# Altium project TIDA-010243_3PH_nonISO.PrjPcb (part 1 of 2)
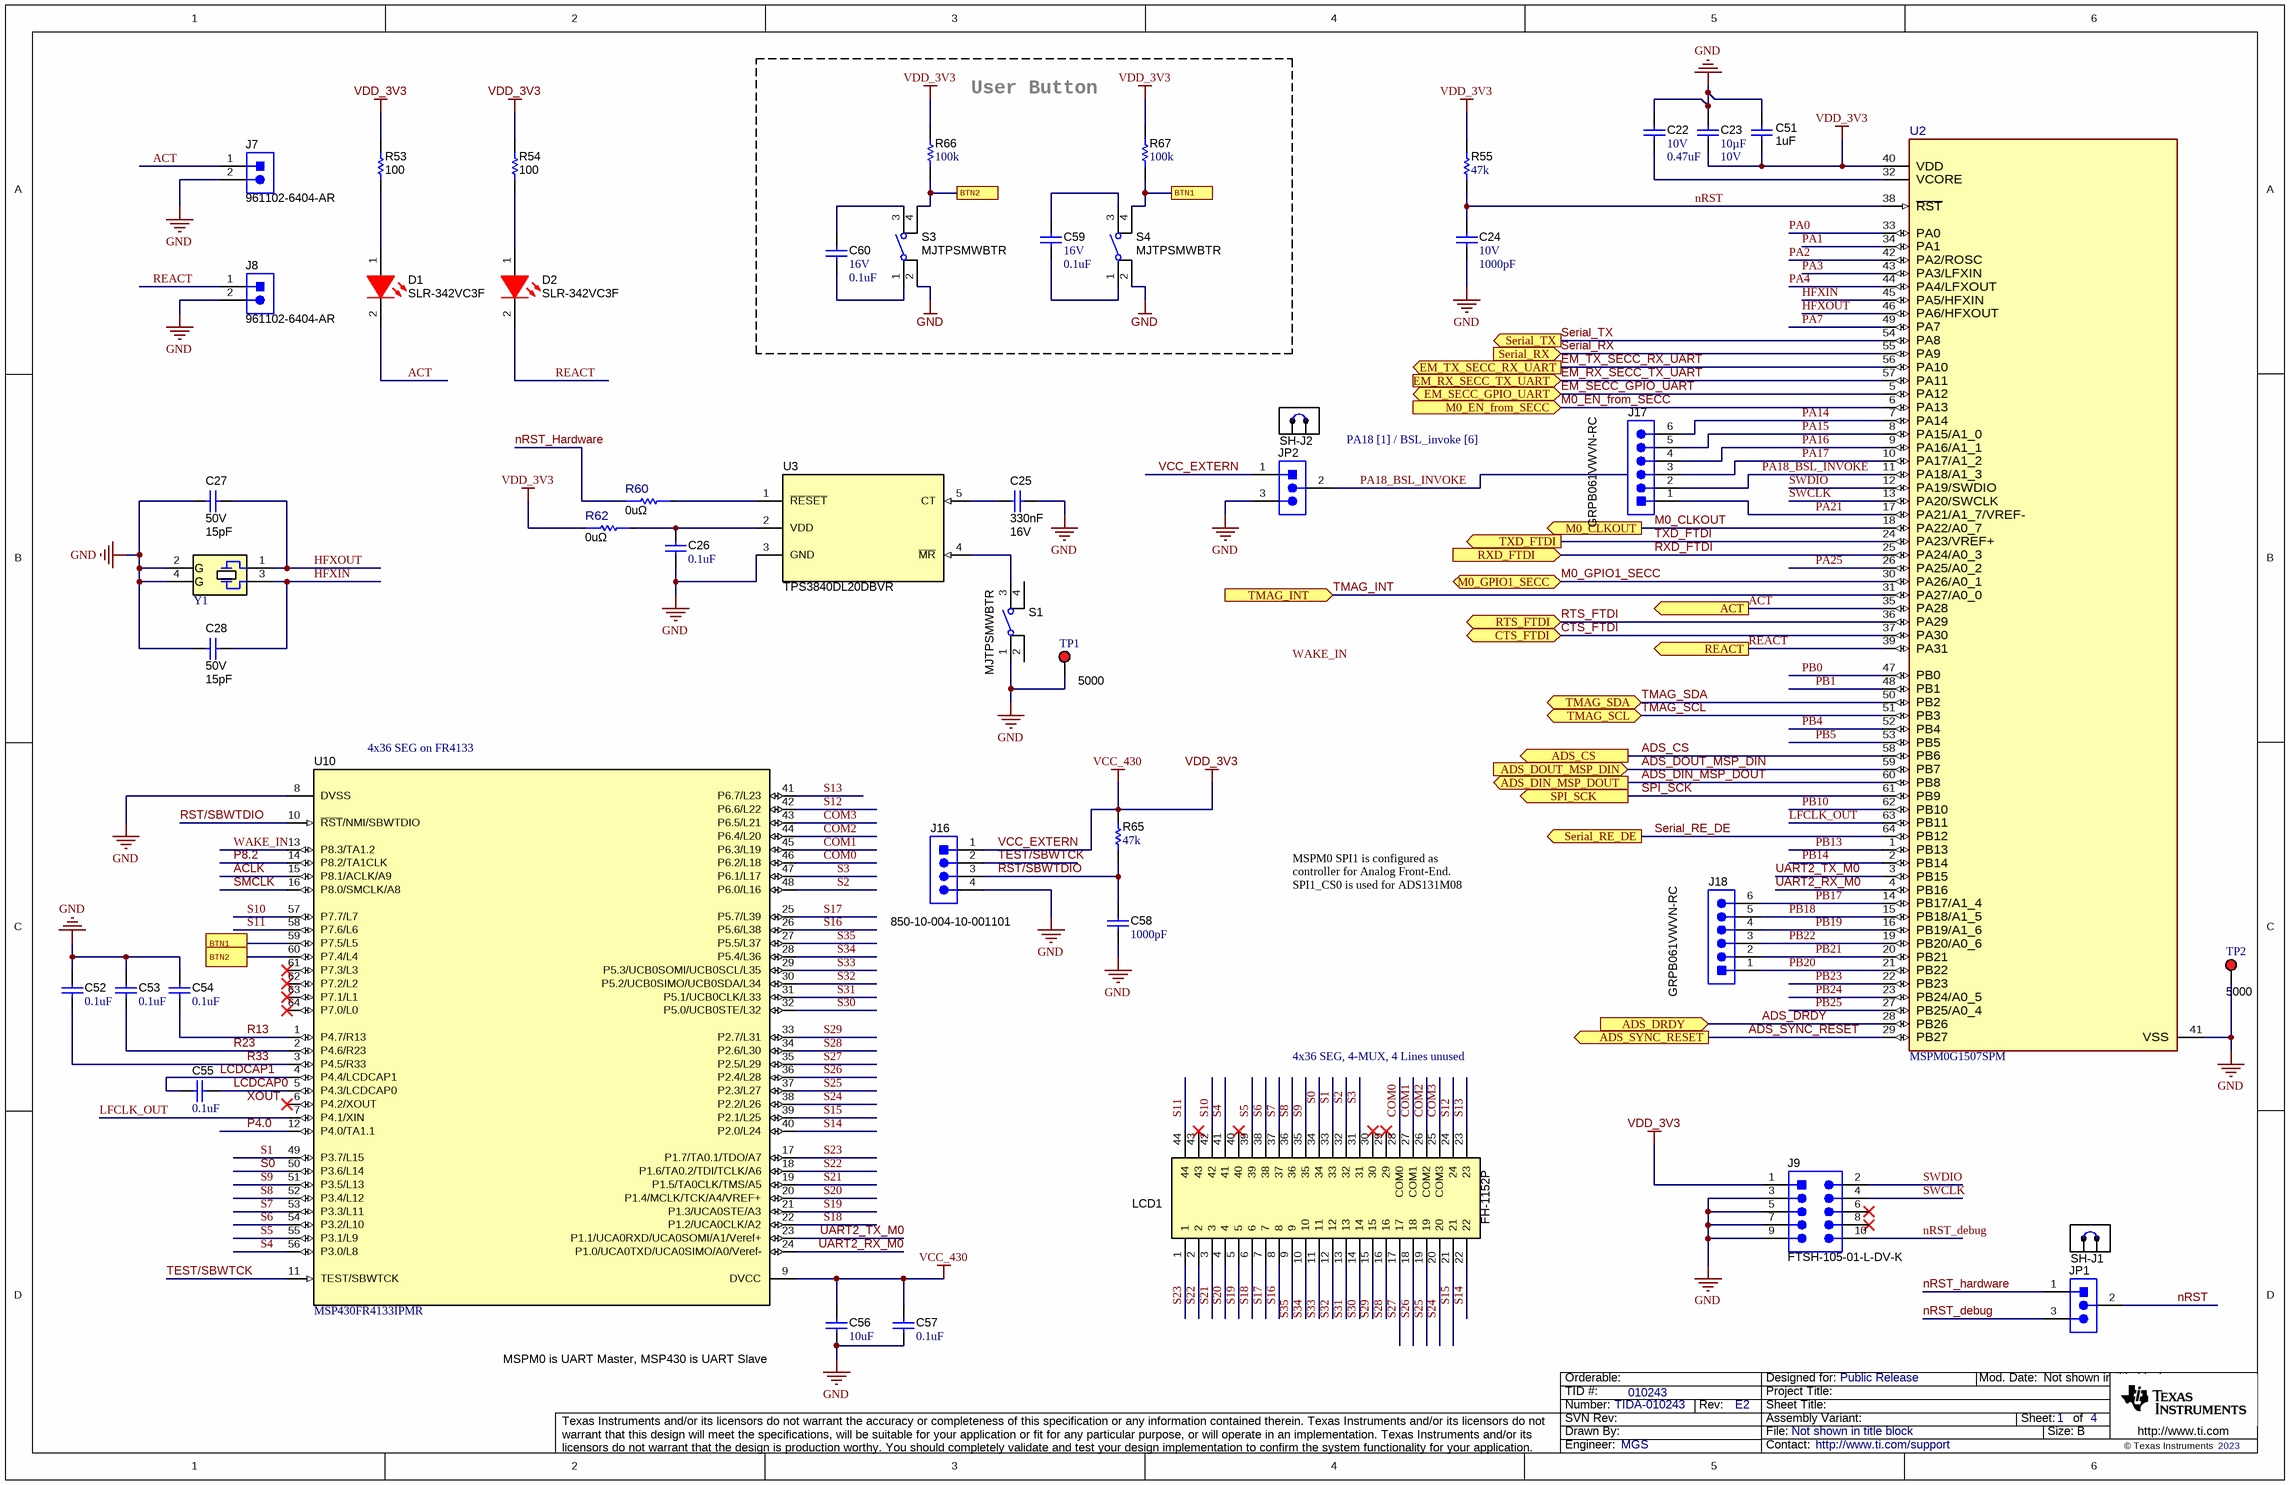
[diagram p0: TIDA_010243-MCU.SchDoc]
3-phase E-meter with CTs: Change in menu Project|Project Options|Parameters; CopyrightYear: 2023; PCB_Layout: a0797195; PCB_Rev: E2; PRJ_Customer: Public Release; PRJ_Engineer: MGS; PRJ_Number: TIDA-010243; SCH_Rev: E2; TechSupport: http://www.ti.com/support; TID: 010243
4 sheets, 215 parts. Net scope: flat (ports and power ports of the same name join across sheets).
Board file: TIDA-010243_3PH_CTnonISO.PcbDoc
Sheets:
  TIDA_010243-MCU.SchDoc
  TIDA-010243-AFE.SchDoc
  TIDA-010243_Interfaces.SchDoc
  TIDA-010243_Hardware.SchDoc

## Sheet TIDA_010243-MCU.SchDoc
size 431 x 279 mm; Date: Not shown in title block; ApprovedBy: Not shown in title block; CheckedBy: Not shown in title block; Author: Not shown in title block; CompanyName: Not shown in title block; Engineer: Not shown in title block; Organization: Not shown in title block; Address1: Not shown in title block; Address2: Not shown in title block; Address3: Not shown in title block; Address4: Not shown in title block; DocumentNumber: 1; Revision: Use project parameter SCH_Rev; SheetNumber: 1; SheetTotal: 4; PageSetup: Record=PageOptions¦CenterHorizontal=True¦CenterVertical=True¦PrintScale=1.00¦XCorrection=1.00¦YCorrection=1.00¦PrintKind=0¦BorderSize=5000000¦LeftOffset=0¦BottomOffset=0¦Orientation=2¦PaperLength=1000¦PaperWidth=1000¦Scale=100¦PaperSource=15¦PrintQuality=600¦MediaType=1¦DitherType=10¦PaperKind=Letter¦PrintScaleMode=1

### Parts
C22  VDC_V: 10V  ValueDisplayed: 0.47uF  [0603]  (hidden comment: GRM188R61A474KA61D)
C23  ValueDisplayed: 10µF  VDC_V: 10V  [0603]  (hidden comment: GRM188R61A106KAALD)
C24  VDC_V: 10V  ValueDisplayed: 1000pF  [0402]  (hidden comment: GRM155R61A102KA01D)
C25  Cap_F: 330nF  VDC_V: 16V  [0603]  (hidden comment: GRM188R71C334KA01D)
C26  value 0.1uF  [0402]  (hidden comment: GCM155R71H104KE02D)
C27  VDC_V: 50V  ValueDisplayed: 15pF  [0402]  (hidden comment: GRM1555C1H150JA01D)
C28  VDC_V: 50V  ValueDisplayed: 15pF  [0402]  (hidden comment: GRM1555C1H150JA01D)
C51  ValueDisplayed: 1uF  [0603]  (hidden comment: C0603C105K3RACTU)
C52  ValueDisplayed: 0.1uF  [0402]  (hidden comment: GCM155R71A104KA55D)
C53  ValueDisplayed: 0.1uF  [0402]  (hidden comment: GCM155R71A104KA55D)
C54  ValueDisplayed: 0.1uF  [0402]  (hidden comment: GCM155R71A104KA55D)
C55  ValueDisplayed: 0.1uF  [0402]  (hidden comment: GCM155R71A104KA55D)
C56  ValueDisplayed: 10uF  [0603]  (hidden comment: GRM188R61A106ME69D)
C57  ValueDisplayed: 0.1uF  [0402]  (hidden comment: GCM155R71A104KA55D)
C58  ValueDisplayed: 1000pF  [0402]  (hidden comment: 885012205044)
C59  VDC_V: 16V  ValueDisplayed: 0.1uF  [0402]  (hidden comment: C0402C104K4RACAUTO)
C60  VDC_V: 16V  ValueDisplayed: 0.1uF  [0402]  (hidden comment: C0402C104K4RACAUTO)
D1  SLR-342VC3F  [SLR-342_Red]
D2  SLR-342VC3F  [SLR-342_Red]
J7  961102-6404-AR  [3M_961102-6404-AR]
J8  961102-6404-AR  [3M_961102-6404-AR]
J9  FTSH-105-01-L-DV-K  [Samtec_FTSH-105-01-x-DV-K]
J16  850-10-004-10-001101  [Preci-dip_850-xx-004-10-001101]
J17  GRPB061VWVN-RC  [Sullins_GRPB061VWVN-RC]
J18  GRPB061VWVN-RC  [Sullins_GRPB061VWVN-RC]
JP1  TSW-103-07-G-S  [TSW-103-07-G-S]  (value not drawn)
JP2  TSW-103-07-G-S  [TSW-103-07-G-S]  (value not drawn)
LCD1  FH-1152P  [ADKOM_FH-1152P]
R53  ValueDisplayed: 100  [0603]  (hidden comment: RC0603FR-07100RL)
R54  ValueDisplayed: 100  [0603]  (hidden comment: RC0603FR-07100RL)
R55  ValueDisplayed: 47k  [0402]  (hidden comment: CRCW040247K0JNED)
R60  value 0uΩ  [FP-CR0402-10W-000T_0402-MFG]  (hidden comment: CR0402-10W-000T)
R62  value 0uΩ  [FP-CR0402-10W-000T_0402-MFG]  (hidden comment: CR0402-10W-000T)
R65  ValueDisplayed: 47k  [0402S]  (hidden comment: CRCW040247K0JNED)
R66  ValueDisplayed: 100k  [0402]  (hidden comment: CRCW0402100KFKED)
R67  ValueDisplayed: 100k  [0402]  (hidden comment: CRCW0402100KFKED)
S1  MJTPSMWBTR  [SW_MJTPSMWB]
S3  MJTPSMWBTR  [SW_MJTPSMWB]
S4  MJTPSMWBTR  [SW_MJTPSMWB]
SH-J1  881545-2  [TE_881545-2]  (value not drawn)  (mechanical)
SH-J2  881545-2  [TE_881545-2]  (value not drawn)  (mechanical)
TP1  5000  [Keystone5000]
TP2  5000  [Keystone5000]
U2  MSPM0G1507SPM  [PM0064A-MFG]
U3  TPS3840DL20DBVR  [DBV0005A_N]
U10  MSP430FR4133IPMR  [PM0064A_L]
Y1  FA-238 16.3840MB-K  [Epson_FA-238]  (value not drawn)

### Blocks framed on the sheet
User Button: C59 C60 R66 R67 S3 S4

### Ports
ACT (out), ADS_CS (out), ADS_DIN_MSP_DOUT (out), ADS_DOUT_MSP_DIN (in), ADS_DRDY (in), ADS_SYNC_RESET (out), BTN1, BTN2, CTS_FTDI (bidir), EM_RX_SECC_TX_UART (in), EM_SECC_GPIO_UART (bidir), EM_TX_SECC_RX_UART (out), M0_CLKOUT (out), M0_EN_from_SECC (in), M0_GPIO1_SECC (bidir), REACT (out), RTS_FTDI (bidir), RXD_FTDI (in), Serial_RE_DE (out), Serial_RX (in), Serial_TX (out), SPI_SCK (out), TMAG_INT (in), TMAG_SCL (bidir), TMAG_SDA (bidir), TXD_FTDI (out)

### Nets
GND: C22.1 C23.1 C24.2 C25.1 C26.1 C27.2 C28.2 C51.2 C52.1 C53.1 C54.1 C56.2 C57.2 C58.2 J7.2 J8.2 J9.3 J9.5 J9.7 J9.9 J16.4 JP2.3 S1.1 S3.2 S4.2 TP1.1 TP2.1 U2.41(VSS) U3.3(GND) U10.8(DVSS) Y1.2(GND) Y1.4(GND)
VCC_EXTERN: C23.2 C51.1 C56.1 C57.1 J9.1 J16.1 JP2.1 R53.2 R54.2 R55.2 R62.1 R65.2 R66.2 R67.2 U2.40(VDD) U10.9(DVCC)  [also labelled VCC_430, VDD_3V3]
ACLK: U10.15(P8.1/ACLK/A9)
ACT: D1.2(K) J7.1 U2.35(PA28) ; port ACT
ADS_CS: U2.58(PB6) ; port ADS_CS
ADS_DIN_MSP_DOUT: U2.60(PB8) ; port ADS_DIN_MSP_DOUT
ADS_DOUT_MSP_DIN: U2.59(PB7) ; port ADS_DOUT_MSP_DIN
ADS_DRDY: U2.28(PB26) ; port ADS_DRDY
ADS_SYNC_RESET: U2.29(PB27) ; port ADS_SYNC_RESET
BTN1: R67.1 S4.4 U10.59(P7.5/L5) ; port BTN1
BTN2: R66.1 S3.4 U10.60(P7.4/L4) ; port BTN2
COM0: LCD1.28(COM0) U10.46(P6.2/L18)
COM1: LCD1.27(COM1) U10.45(P6.3/L19)
COM2: LCD1.26(COM2) U10.44(P6.4/L20)
COM3: LCD1.25(COM3) U10.43(P6.5/L21)
CTS_FTDI: U2.37(PA30) ; port CTS_FTDI
EM_RX_SECC_TX_UART: U2.57(PA11) ; port EM_RX_SECC_TX_UART
EM_SECC_GPIO_UART: U2.5(PA12) ; port EM_SECC_GPIO_UART
EM_TX_SECC_RX_UART: U2.56(PA10) ; port EM_TX_SECC_RX_UART
HFXIN: C28.1 U2.45(PA5/HFXIN) Y1.3
HFXOUT: C27.1 U2.46(PA6/HFXOUT) Y1.1
LCDCAP0: C55.2 U10.5(P4.3/LCDCAP0)
LCDCAP1: C55.1 U10.4(P4.4/LCDCAP1)
LFCLK_OUT: U2.63(PB11) U10.7(P4.1/XIN)
M0_CLKOUT: U2.18(PA22/A0_7) ; port M0_CLKOUT
M0_EN_from_SECC: U2.6(PA13) ; port M0_EN_from_SECC
M0_GPIO1_SECC: U2.30(PA26/A0_1) ; port M0_GPIO1_SECC
nRST: C24.1 JP1.2 R55.1 U2.38(~{RST})
nRST_debug: J9.10 JP1.3
nRST_Hardware: JP1.1 R60.1
P4.0: U10.12(P4.0/TA1.1)
P8.2: U10.14(P8.2/TA1CLK)
PA0: U2.33(PA0)
PA1: U2.34(PA1)
PA2: U2.42(PA2/ROSC)
PA3: U2.43(PA3/LFXIN)
PA4: U2.44(PA4/LFXOUT)
PA7: U2.49(PA7)
PA14: J17.6 U2.7(PA14)
PA15: J17.5 U2.8(PA15/A1_0)
PA16: J17.4 U2.9(PA16/A1_1)
PA17: J17.3 U2.10(PA17/A1_2)
PA18_BSL_INVOKE: J17.2 JP2.2 U2.11(PA18/A1_3)
PA21: J17.1 U2.17(PA21/A1_7/VREF-)
PA25: U2.26(PA25/A0_2)
PB0: U2.47(PB0)
PB1: U2.48(PB1)
PB4: U2.52(PB4)
PB5: U2.53(PB5)
PB10: U2.62(PB10)
PB13: U2.1(PB13)
PB14: U2.2(PB14)
PB17: J18.6 U2.14(PB17/A1_4)
PB18: J18.5 U2.15(PB18/A1_5)
PB19: J18.4 U2.16(PB19/A1_6)
PB20: J18.1 U2.21(PB22)
PB21: J18.2 U2.20(PB21)
PB22: J18.3 U2.19(PB20/A0_6)
PB23: U2.22(PB23)
PB24: U2.23(PB24/A0_5)
PB25: U2.27(PB25/A0_4)
R13: C54.2 U10.1(P4.7/R13)
R23: C53.2 U10.2(P4.6/R23)
R33: C52.2 U10.3(P4.5/R33)
REACT: D2.2(K) J8.1 U2.39(PA31) ; port REACT
RST/SBWTDIO: C58.1 J16.3 R65.1 U10.10(~{RST}/NMI/SBWTDIO)
RTS_FTDI: U2.36(PA29) ; port RTS_FTDI
RXD_FTDI: U2.25(PA24/A0_3) ; port RXD_FTDI
S0: LCD1.34 U10.50(P3.6/L14)
S1: LCD1.33 U10.49(P3.7/L15)
S2: LCD1.32 U10.48(P6.0/L16)
S3: LCD1.31 U10.47(P6.1/L17)
S4: LCD1.41 U10.56(P3.0/L8)
S5: LCD1.39 U10.55(P3.1/L9)
S6: LCD1.38 U10.54(P3.2/L10)
S7: LCD1.37 U10.53(P3.3/L11)
S8: LCD1.36 U10.52(P3.4/L12)
S9: LCD1.35 U10.51(P3.5/L13)
S10: LCD1.42 U10.57(P7.7/L7)
S11: LCD1.44 U10.58(P7.6/L6)
S12: LCD1.24 U10.42(P6.6/L22)
S13: LCD1.23 U10.41(P6.7/L23)
S14: LCD1.22 U10.40(P2.0/L24)
S15: LCD1.21 U10.39(P2.1/L25)
S16: LCD1.8 U10.26(P5.6/L38)
S17: LCD1.7 U10.25(P5.7/L39)
S18: LCD1.6 U10.22(P1.2/UCA0CLK/A2)
S19: LCD1.5 U10.21(P1.3/UCA0STE/A3)
S20: LCD1.4 U10.20(P1.4/MCLK/TCK/A4/VREF+)
S21: LCD1.3 U10.19(P1.5/TA0CLK/TMS/A5)
S22: LCD1.2 U10.18(P1.6/TA0.2/TDI/TCLK/A6)
S23: LCD1.1 U10.17(P1.7/TA0.1/TDO/A7)
S24: LCD1.20 U10.38(P2.2/L26)
S25: LCD1.19 U10.37(P2.3/L27)
S26: LCD1.18 U10.36(P2.4/L28)
S27: LCD1.17 U10.35(P2.5/L29)
S28: LCD1.16 U10.34(P2.6/L30)
S29: LCD1.15 U10.33(P2.7/L31)
S30: LCD1.14 U10.32(P5.0/UCB0STE/L32)
S31: LCD1.13 U10.31(P5.1/UCB0CLK/L33)
S32: LCD1.12 U10.30(P5.2/UCB0SIMO/UCB0SDA/L34)
S33: LCD1.11 U10.29(P5.3/UCB0SOMI/UCB0SCL/L35)
S34: LCD1.10 U10.28(P5.4/L36)
S35: LCD1.9 U10.27(P5.5/L37)
Serial_RE_DE: U2.64(PB12) ; port Serial_RE_DE
Serial_RX: U2.55(PA9) ; port Serial_RX
Serial_TX: U2.54(PA8) ; port Serial_TX
SMCLK: U10.16(P8.0/SMCLK/A8)
SPI_SCK: U2.61(PB9) ; port SPI_SCK
SWCLK: J9.4 U2.13(PA20/SWCLK)
SWDIO: J9.2 U2.12(PA19/SWDIO)
TEST/SBWTCK: J16.2 U10.11(TEST/SBWTCK)
TMAG_INT: U2.31(PA27/A0_0) ; port TMAG_INT
TMAG_SCL: U2.51(PB3) ; port TMAG_SCL
TMAG_SDA: U2.50(PB2) ; port TMAG_SDA
TXD_FTDI: U2.24(PA23/VREF+) ; port TXD_FTDI
UART2_RX_M0: U2.4(PB16) U10.24(P1.0/UCA0TXD/UCA0SIMO/A0/Veref-)
UART2_TX_M0: U2.3(PB15) U10.23(P1.1/UCA0RXD/UCA0SOMI/A1/Veref+)
WAKE_IN: U10.13(P8.3/TA1.2)
NetC22_2: C22.2 U2.32(VCORE)
NetC25_2: C25.2 U3.5(CT)
NetC26_2: C26.2 R62.2 U3.2(VDD)
NetC59_1: C59.1 S4.3
NetC59_2: C59.2 S4.1
NetC60_1: C60.1 S3.3
NetC60_2: C60.2 S3.1
NetD1_1: D1.1(A) R53.1
NetD2_1: D2.1(A) R54.1
NetR60_2: R60.2 U3.1(~{RESET})
NetS1_3: S1.3 U3.4(~{MR})

Not connected (* = marked no-connect by the designer): J9 6* 8*; LCD1 29* 30* 40* 43*; S1 2 4; U10 6(P4.2/XOUT)* 61(P7.3/L3)* 62(P7.2/L2)* 63(P7.1/L1)* 64(P7.0/L0)*

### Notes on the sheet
- PA18 [1] / BSL_invoke [6]
- (near U10) 4x36 SEG on FR4133
- MSPM0 SPI1 is configured as controller for Analog Front-End. SPI1_CS0 is used for ADS131M08
- 4x36 SEG, 4-MUX, 4 Lines unused
- MSPM0 is UART Master, MSP430 is UART Slave
- Labels drawn without touching a wire or pin: WAKE_IN, XOUT

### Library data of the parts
C22 = CMP-0007328-5: CAP, CERM, 0.47 uF, 10 V, +/- 10%, X5R, 0603; Manufacturer: MuRata; TaMin_C: -55°C; Polarized: N; SizeAreaWB_mm2: 4.68; Value1: Unknown; U/M: EA; Value: 0.47uF; TaMax_C: 85°C; SizeZ_mm: 1; SizeX_mm: 1.6; SizeY_mm: 0.8; SizeArea_mm2: 1.28; Cap_F: 470nF; AEC Category: Q200
C23 = CMP-0086193-1: CAP, CERM, 10 µF, 10 V,+/- 10%, X5R, 0603; Manufacturer: MuRata; SizeArea_mm2: 1.28; SizeY_mm: 0.8; TaMax_C: 85°C; TaMin_C: -55°C; Polarized: N; SizeAreaWB_mm2: 4.68; SizeZ_mm: 1; SizeX_mm: 1.6; AEC Category: Q200; U/M: EA; Value: 10uF
C24 = CMP-0006560-2: CAP, CERM, 1000 pF, 10 V, +/- 10%, X5R, 0402; Manufacturer: MuRata; TaMin_C: -55°C; Polarized: N; SizeAreaWB_mm2: 3; Value1: Unknown; U/M: EA; Value: 1000pF; TaMax_C: 85°C; SizeZ_mm: 0.6; SizeX_mm: 1; SizeY_mm: 0.5; Cap_F: 1nF; AEC Category: Q200
C25 = CMP-0007393-1: CAP, CERM, 0.33 uF, 16 V, +/- 10%, X7R, 0603; Manufacturer: MuRata; TaMin_C: -55°C; Polarized: N; SizeAreaWB_mm2: 4.68; Value1: Unknown; U/M: EA; Value: 0.33uF; TaMax_C: 125°C; SizeZ_mm: 1; SizeX_mm: 1.6; SizeY_mm: 0.8; SizeArea_mm2: 1.28; AEC Category: Q200
C26 = CMP-0006356-2: CAP, CERM, 0.1 uF, 50 V, +/- 10%, X7R, AEC-Q200 Grade 1, 0402; Manufacturer: MuRata; TaMin_C: -55°C; Polarized: N; SizeAreaWB_mm2: 3; Value1: Unknown; U/M: EA; TaMax_C: 125°C; SizeZ_mm: 0.6; SizeX_mm: 1; SizeY_mm: 0.5; Value2: 50V; AEC Qualified: Y; AEC Category: Q200; Cap_F: 100nF
C27 C28 = CMP-0006420-2: CAP, CERM, 15 pF, 50 V, +/- 5%, C0G/NP0, 0402; Manufacturer: MuRata; TaMin_C: -55°C; Polarized: N; SizeAreaWB_mm2: 3; Value1: Unknown; U/M: EA; Value: 15pF; TaMax_C: 125°C; SizeZ_mm: 0.6; SizeX_mm: 1; SizeY_mm: 0.5; AEC Category: Q200
C51 = CMP-0006867-4: CAP, CERM, 1 uF, 25 V, +/- 10%, X7R, 0603; Manufacturer: Kemet; TaMin_C: -55°C; Polarized: N; SizeAreaWB_mm2: 4.68; Value1: Unknown; U/M: EA; Value: 1uF; TaMax_C: 125°C; SizeZ_mm: 1; SizeX_mm: 1.6; SizeY_mm: 0.8; Value2: 25V; SizeArea_mm2: 1.28; CompType: Capacitor; Cap_F: 1µF; AEC Category: Q200
C52-C55 C57 = CMP-0006350-2: CAP, CERM, 0.1 uF, 10 V, +/- 10%, X7R, AEC-Q200 Grade 1, 0402; Manufacturer: MuRata; Polarized: N; Value: 0.1uF; U/M: EA; Cap_F: 100nF; Value1: Unknown; VDC_V: 10V; TaMin_C: -55°C; TaMax_C: 125°C; SizeAreaWB_mm2: 3; SizeZ_mm: 0.6; SizeX_mm: 1; SizeY_mm: 0.5; AEC Qualified: Y; AEC Category: Q200
C56 = CMP-0007318-5: CAP, CERM, 10 uF, 10 V, +/- 20%, X5R, 0603; Manufacturer: MuRata; Polarized: N; Value: 10uF; U/M: EA; Cap_F: 10µF; Value1: Unknown; VDC_V: 10V; TaMin_C: -55°C; TaMax_C: 85°C; SizeAreaWB_mm2: 4.68; SizeZ_mm: 1; SizeX_mm: 1.6; SizeY_mm: 0.8; SizeArea_mm2: 1.28; AEC Category: Q200
C58 = CMP-0006229-2: CAP, CERM, 1000 pF, 25 V, +/- 10%, X7R, 0402; Manufacturer: Wurth Elektronik; Polarized: N; Value: 1000pF; U/M: EA; Cap_F: 1nF; Value1: Unknown; VDC_V: 25V; TaMin_C: -55°C; TaMax_C: 125°C; SizeAreaWB_mm2: 3; SizeZ_mm: 0.6; SizeX_mm: 1; SizeY_mm: 0.5; AEC Category: Q200
C59 C60 = CMP-0006237-2: CAP, CERM, 0.1 uF, 16 V, +/- 10%, X7R, AEC-Q200 Grade 1, 0402; Manufacturer: Kemet; TaMin_C: -55°C; Polarized: N; SizeAreaWB_mm2: 3; Value1: Unknown; U/M: EA; Value: 0.1uF; TaMax_C: 125°C; SizeZ_mm: 0.6; SizeX_mm: 1; SizeY_mm: 0.5; AEC Qualified: Y; Cap_F: 100nF; AEC Category: Q200
D1 D2 = CMP-0079280-1: LED, Red, TH; Manufacturer: Rohm; SizeAreaWB_mm2: 23.04; Vr_V: 3V; Power_TotalModule: 60mW; Angle: 40; SizeArea_mm2: 14.44; Ir_A: 10µA; SizeZ_mm: 6.35; Io_A: 10mA; Vf_V: 2V; SizeY_mm: 3.8; Value1: 0.06W; Type: GaAsP on GaP
J7 J8 = CMP-0075197-1: Header, 2.54mm, 2x1, TH; Manufacturer: 3M; CNHeader: True; Current_A: 2A; Green_Lifecycle: Active; Shrouded: N; Gender: Male; Green_REACh: Passed; Voltage_V: 1kV; Row_Count: 1; Pitch_mm: 2.54; ContactFinish: Gold; CT: False; Cert_UL: Y
J9 = CMP-0075634-2: Header(Shrouded), 1.27mm, 5x2, Gold, SMT; Manufacturer: Samtec; Pitch_mm: 1.27; Gender: Male; Cert_CSA: Y; Current_A: 3.3A; Row_Count: 2
J16 = CMP-0074999-1: Header, 50mil, 4x1, Gold, TH; Manufacturer: Preci-Dip; CT: False; CNHeader: True
J17 J18 = CMP-0054561-1: Header, 50mil, 6x1, Gold,  TH; Manufacturer: Sullins Connector Solutions; CT: FALSE; CNHeader: TRUE
JP1 JP2 = CMP-0075407-2: Header, 100mil, 3x1, Gold, TH; Manufacturer: Samtec; Pitch_mm: 2.54; Cert_VDE: N; Gender: Male; Cert_CSA: Y; Voltage_V: 550V; Green_REACh: Passed; Current_A: 6.3A; Green_Lifecycle: Active; Row_Count: 1
LCD1 = CMP-0079272-1: 160 Segment LCD Display, TH; Manufacturer: Adkom Elektronik; SizeArea_mm2: 1970.56; SizeAreaWB_mm2: 2164.14; SizeY_mm: 64; SizeZ_mm: 3.1; SizeX_mm: 30.79
R53 R54 = CMP-0022736-2: RES, 100, 1%, 0.1 W, 0603; Manufacturer: Yageo America; Power_W: 100mW; TempCo: 200 ppm/C; Value_Code: 100R; U/M: EA; Value: 100; EIA_Code: E96; SizeX_mm: 1.6; SizeY_mm: 0.8; SizeZ_mm: 1; Value2: 0.1W; SizeArea_mm2: 1.28; VDC_V: 150V; AEC Category: Q200
R55 = CMP-0026935-3: RES, 47 k, 5%, 0.063 W, AEC-Q200 Grade 0, 0402; Manufacturer: Vishay-Dale; Power_W: 63mW; TempCo: 200 ppm/C; Value_Code: 47k0; Value: 47k; EIA_Code: E24; SizeX_mm: 1; SizeY_mm: 0.5; SizeZ_mm: 0.6; Value2: 0.063W; AEC Qualified: Y; VDC_V: 50V; AEC Category: Q200; AEC Grade: 0
R60 R62 = CMP-0094948-1: 0 Ohms Jumper 0.1W, 1/10W Chip Resistor 0402 (1005 Metric) - Thick Film; Manufacturer: Venkel; AEC Qualified: No; VDC_V: 50V; SizeZ_mm: 0.4mm; Res_ohm: 0; Power_W: 100mW
R65 = CMP-0026935-3: RES, 47 k, 5%, 0.063 W, AEC-Q200 Grade 0, 0402; Manufacturer: Vishay-Dale; Value: 47k; Value_Code: 47k0; Power_W: 63mW; Value2: 0.063W; VDC_V: 50V; TempCo: 200 ppm/C; EIA_Code: E24; SizeX_mm: 1; SizeY_mm: 0.5; SizeZ_mm: 0.6; AEC Qualified: Y; AEC Category: Q200; AEC Grade: 0
R66 R67 = CMP-0025950-3: RES, 100 k, 1%, 0.063 W, AEC-Q200 Grade 0, 0402; Manufacturer: Vishay-Dale; Power_W: 63mW; TempCo: 100 ppm/C; Value: 100k; EIA_Code: E96; SizeX_mm: 1; SizeY_mm: 0.5; SizeZ_mm: 0.6; Value2: 0.063W; AEC Qualified: Y; AEC Category: Q200; AEC Grade: 0; VDC_V: 50V
S1 S3 S4 = CMP-0002197-2: Switch, Tactile, SPST-NO, 12 V, SMD; Manufacturer: APEM; CurrentRating_mA: 50A; PositionCount: 1; VDC_V: 12V; SwitchFunction: Off-Mom
SH-J1 SH-J2 = 881545-2: Shunt, 100mil, Gold plated, Black; Manufacturer: TE Connectivity
TP1 TP2 = CMP-0055137-1: Test Point, Miniature, Red, TH; Manufacturer: Keystone; CNHeader: FALSE; Green_Lifecycle: Active; Green_REACh: Passed; ContactFinish: Silver; CT: TRUE
U2 = CMP-0093955-1: Mixed-Signal Microcontrollers LQFP64 80MHz 128KB Flash and 32KB RAM 60 GPIO's 32bits ARM Cortex-M0+ 7 Timers; Manufacturer: Texas Instruments; AEC Qualified: No; TJmax_C: +130°C; TaMax_C: +125°C; Number Of Cores: 1; Number Of Adc Channels: 16; TaMin_C: -40°C; Number Of I2C Channels: 2; Number Of Uart Channels: 4; Number Of Timers/Counters: 7; SizeZ_mm: 1.6mm; Number Of Pwm Channels: 14; Ram Size: 32KBytes; Max Supply Voltage: 3.6V; Memory Size: 128KBytes; Standoff Height: 0.05mm; Interface: I2C,SPI,UART,LIN,IrDA,SMBus; Number Of I/Os: 60; Min Supply Voltage: 1.62V
U3 = CMP-0084477-1: Nano Power, Wide VIN Voltage Detector with Programmable Delay, DBV0005A (SOT-23-5); Manufacturer: Texas Instruments; SizeAreaWB_mm2: 14.82; SizeArea_mm2: 8.12; AEC Qualified: N; SizeY_mm: 2.9; AEC Category: Q200; CompType: IC; SizeZ_mm: 1.45; SizeX_mm: 2.8
U10 = CMP-0076610-2: 16 MHz Ultra-Low-Power Microcontroller with 16 KB FRAM, 2 KB SRAM, 60 IO, 10 ch ADC10, LCD, IR Logic, PM0064A (LQFP-64); Manufacturer: Texas Instruments; SizeZ_mm: 1.6; SizeX_mm: 12.0; SizeArea_mm2: 144.0; CompType: IC; U/M: EA; SizeAreaWB_mm2: 196.0
Y1 = CMP-0085525-1: Crystal, 16.384 MHz, 50 ppm, 10 pF, SMD; Manufacturer: Epson; SizeArea_mm2: 8; SizeAreaWB_mm2: 14.7; SizeZ_mm: 0.7; Load Capacitance: 10 pF; AEC Qualified: N; Frequency Stability: 30 ppm; TaMax_C: 70°C; SizeY_mm: 3.2; Frequency Tolerance: 50 ppm; SizeX_mm: 2.5; AEC Category: Q200; TaMin_C: -20°C

## Sheet TIDA-010243-AFE.SchDoc
size 431 x 279 mm; Date: Not shown in title block; ApprovedBy: Not shown in title block; CheckedBy: Not shown in title block; Author: Not shown in title block; CompanyName: Not shown in title block; Engineer: Not shown in title block; Organization: Not shown in title block; Address1: Not shown in title block; Address2: Not shown in title block; Address3: Not shown in title block; Address4: Not shown in title block; DocumentNumber: 2; Revision: Use project parameter SCH_Rev; SheetNumber: 2; SheetTotal: 4; PageSetup: Record=PageOptions¦CenterHorizontal=True¦CenterVertical=True¦PrintScale=1.00¦XCorrection=1.00¦YCorrection=1.00¦PrintKind=0¦BorderSize=5000000¦LeftOffset=0¦BottomOffset=0¦Orientation=2¦PaperLength=1000¦PaperWidth=1000¦Scale=100¦PaperSource=15¦PrintQuality=600¦MediaType=1¦DitherType=10¦PaperKind=Letter¦PrintScaleMode=1
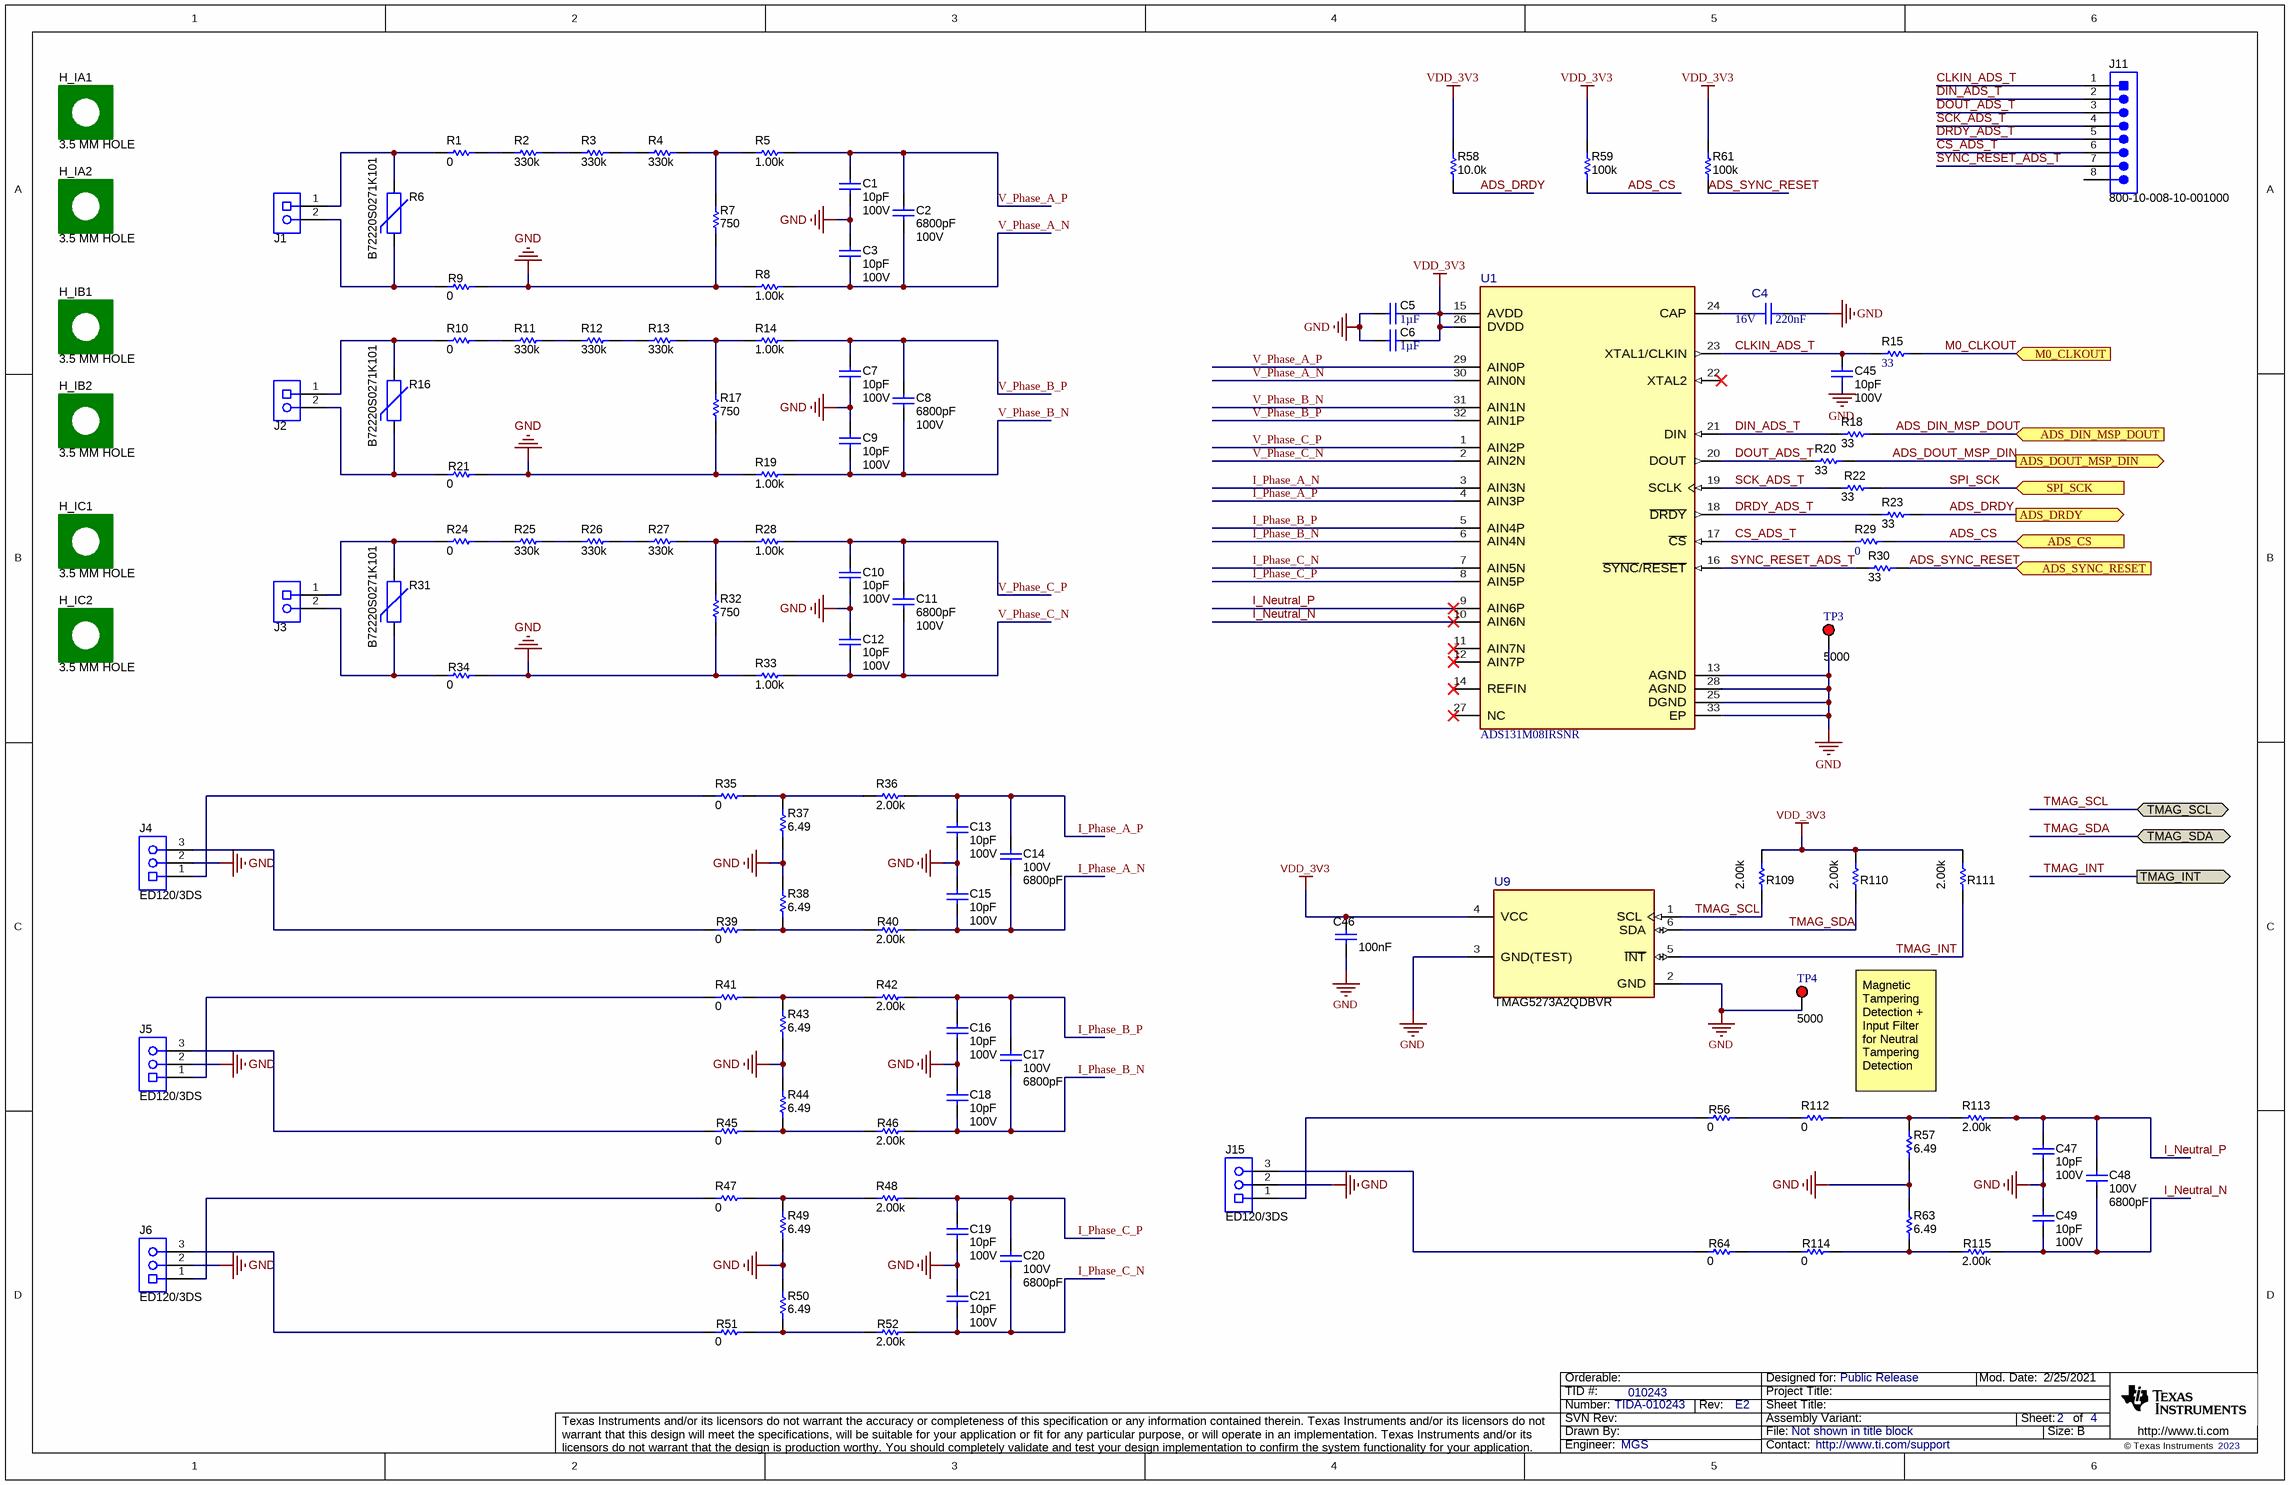
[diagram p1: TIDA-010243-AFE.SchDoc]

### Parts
C1  ValueDisplayed: 10pF  VDC_V: 100V  [0603]  (hidden comment: GCM1885C2A100JA16D)
C2  ValueDisplayed: 6800pF  VDC_V: 100V  [0603]  (hidden comment: CGA3EANP02A682J080AC)
C3  ValueDisplayed: 10pF  VDC_V: 100V  [0603]  (hidden comment: GCM1885C2A100JA16D)
C4  ValueDisplayed: 220nF  VDC_V: 16V  [FP-CGA2B2X7R1C224K050BE_0402-MFG]  (hidden comment: CGA2B2X7R1C224K050BE)
C5  Cap_F: 1µF  [0603]  (hidden comment: CGA3E1X7R1C105K080AC)
C6  Cap_F: 1µF  [0603]  (hidden comment: CGA3E1X7R1C105K080AC)
C7  ValueDisplayed: 10pF  VDC_V: 100V  [0603]  (hidden comment: GCM1885C2A100JA16D)
C8  ValueDisplayed: 6800pF  VDC_V: 100V  [0603]  (hidden comment: CGA3EANP02A682J080AC)
C9  ValueDisplayed: 10pF  VDC_V: 100V  [0603]  (hidden comment: GCM1885C2A100JA16D)
C10  ValueDisplayed: 10pF  VDC_V: 100V  [0603]  (hidden comment: GCM1885C2A100JA16D)
C11  ValueDisplayed: 6800pF  VDC_V: 100V  [0603]  (hidden comment: CGA3EANP02A682J080AC)
C12  ValueDisplayed: 10pF  VDC_V: 100V  [0603]  (hidden comment: GCM1885C2A100JA16D)
C13  ValueDisplayed: 10pF  VDC_V: 100V  [0603]  (hidden comment: GCM1885C2A100JA16D)
C14  VDC_V: 100V  ValueDisplayed: 6800pF  [0603]
C15  ValueDisplayed: 10pF  VDC_V: 100V  [0603]  (hidden comment: GCM1885C2A100JA16D)
C16  ValueDisplayed: 10pF  VDC_V: 100V  [0603]  (hidden comment: GCM1885C2A100JA16D)
C17  VDC_V: 100V  ValueDisplayed: 6800pF  [0603]
C18  ValueDisplayed: 10pF  VDC_V: 100V  [0603]  (hidden comment: GCM1885C2A100JA16D)
C19  ValueDisplayed: 10pF  VDC_V: 100V  [0603]  (hidden comment: GCM1885C2A100JA16D)
C20  VDC_V: 100V  ValueDisplayed: 6800pF  [0603]
C21  ValueDisplayed: 10pF  VDC_V: 100V  [0603]  (hidden comment: GCM1885C2A100JA16D)
C45  ValueDisplayed: 10pF  VDC_V: 100V  [0603]  (hidden comment: GCM1885C2A100JA16D)
C46  Cap_F: 100nF  [0603]  (hidden comment: C0603X104K3RACTU)
C47  ValueDisplayed: 10pF  VDC_V: 100V  [0603]  (hidden comment: GCM1885C2A100JA16D)
C48  VDC_V: 100V  ValueDisplayed: 6800pF  [0603]
C49  ValueDisplayed: 10pF  VDC_V: 100V  [0603]  (hidden comment: GCM1885C2A100JA16D)
H_IA1  3.5 MM HOLE  [3_5MM_HOLE]
H_IA2  3.5 MM HOLE  [3_5MM_HOLE]
H_IB1  3.5 MM HOLE  [3_5MM_HOLE]
H_IB2  3.5 MM HOLE  [3_5MM_HOLE]
H_IC1  3.5 MM HOLE  [3_5MM_HOLE]
H_IC2  3.5 MM HOLE  [3_5MM_HOLE]
J1  ED120/2DS  [On-Shore_ED120_2DS]  (value not drawn)
J2  ED120/2DS  [On-Shore_ED120_2DS]  (value not drawn)
J3  ED120/2DS  [On-Shore_ED120_2DS]  (value not drawn)
J4  ED120/3DS  [On-Shore_ED120_3DS]
J5  ED120/3DS  [On-Shore_ED120_3DS]
J6  ED120/3DS  [On-Shore_ED120_3DS]
J11  800-10-008-10-001000  [Mill-Max_800-10-008-10-001000]
J15  ED120/3DS  [On-Shore_ED120_3DS]
R1  ValueDisplayed: 0  [0603]  (hidden comment: ERJ-3GEY0R00V)
R2  ValueDisplayed: 330k  [0603]  (hidden comment: RG1608P-334-B-T5)
R3  ValueDisplayed: 330k  [0603]  (hidden comment: RG1608P-334-B-T5)
R4  ValueDisplayed: 330k  [0603]  (hidden comment: RG1608P-334-B-T5)
R5  ValueDisplayed: 1.00k  [0603]  (hidden comment: RT0603DRD071KL)
R6  B72220S0271K101  [Epcos_B72220S0271K101]
R7  ValueDisplayed: 750  [0603]  (hidden comment: RT0603DRE07750RL)
R8  ValueDisplayed: 1.00k  [0603]  (hidden comment: RT0603DRD071KL)
R9  ValueDisplayed: 0  [0603]  (hidden comment: ERJ-3GEY0R00V)
R10  ValueDisplayed: 0  [0603]  (hidden comment: ERJ-3GEY0R00V)
R11  ValueDisplayed: 330k  [0603]  (hidden comment: RG1608P-334-B-T5)
R12  ValueDisplayed: 330k  [0603]  (hidden comment: RG1608P-334-B-T5)
R13  ValueDisplayed: 330k  [0603]  (hidden comment: RG1608P-334-B-T5)
R14  ValueDisplayed: 1.00k  [0603]  (hidden comment: RT0603DRD071KL)
R15  ValueDisplayed: 33  [0402]  (hidden comment: CRCW040233R0JNED)
R16  B72220S0271K101  [Epcos_B72220S0271K101]
R17  ValueDisplayed: 750  [0603]  (hidden comment: RT0603DRE07750RL)
R18  ValueDisplayed: 33  [0402]  (hidden comment: CRCW040233R0JNED)
R19  ValueDisplayed: 1.00k  [0603]  (hidden comment: RT0603DRD071KL)
R20  ValueDisplayed: 33  [0402]  (hidden comment: CRCW040233R0JNED)
R21  ValueDisplayed: 0  [0603]  (hidden comment: ERJ-3GEY0R00V)
R22  ValueDisplayed: 33  [0402]  (hidden comment: CRCW040233R0JNED)
R23  ValueDisplayed: 33  [0402]  (hidden comment: CRCW040233R0JNED)
R24  ValueDisplayed: 0  [0603]  (hidden comment: ERJ-3GEY0R00V)
R25  ValueDisplayed: 330k  [0603]  (hidden comment: RG1608P-334-B-T5)
R26  ValueDisplayed: 330k  [0603]  (hidden comment: RG1608P-334-B-T5)
R27  ValueDisplayed: 330k  [0603]  (hidden comment: RG1608P-334-B-T5)
R28  ValueDisplayed: 1.00k  [0603]  (hidden comment: RT0603DRD071KL)
R29  ValueDisplayed: 0  [0402]  (hidden comment: CRCW04020000Z0ED)
R30  ValueDisplayed: 33  [0402]  (hidden comment: CRCW040233R0JNED)
R31  B72220S0271K101  [Epcos_B72220S0271K101]
R32  ValueDisplayed: 750  [0603]  (hidden comment: RT0603DRE07750RL)
R33  ValueDisplayed: 1.00k  [0603]  (hidden comment: RT0603DRD071KL)
R34  ValueDisplayed: 0  [0603]  (hidden comment: ERJ-3GEY0R00V)
R35  ValueDisplayed: 0  [0603]  (hidden comment: ERJ-3GEY0R00V)
R36  ValueDisplayed: 2.00k  [0603]  (hidden comment: RT0603DRD072KL)
R37  ValueDisplayed: 6.49  [0603]  (hidden comment: CRCW06036R49FKEA)
R38  ValueDisplayed: 6.49  [0603]  (hidden comment: CRCW06036R49FKEA)
R39  ValueDisplayed: 0  [0603]  (hidden comment: ERJ-3GEY0R00V)
R40  ValueDisplayed: 2.00k  [0603]  (hidden comment: RT0603DRD072KL)
R41  ValueDisplayed: 0  [0603]  (hidden comment: ERJ-3GEY0R00V)
R42  ValueDisplayed: 2.00k  [0603]  (hidden comment: RT0603DRD072KL)
R43  ValueDisplayed: 6.49  [0603]  (hidden comment: CRCW06036R49FKEA)
R44  ValueDisplayed: 6.49  [0603]  (hidden comment: CRCW06036R49FKEA)
R45  ValueDisplayed: 0  [0603]  (hidden comment: ERJ-3GEY0R00V)
R46  ValueDisplayed: 2.00k  [0603]  (hidden comment: RT0603DRD072KL)
R47  ValueDisplayed: 0  [0603]  (hidden comment: ERJ-3GEY0R00V)
R48  ValueDisplayed: 2.00k  [0603]  (hidden comment: RT0603DRD072KL)
R49  ValueDisplayed: 6.49  [0603]  (hidden comment: CRCW06036R49FKEA)
R50  ValueDisplayed: 6.49  [0603]  (hidden comment: CRCW06036R49FKEA)
R51  ValueDisplayed: 0  [0603]  (hidden comment: ERJ-3GEY0R00V)
R52  ValueDisplayed: 2.00k  [0603]  (hidden comment: RT0603DRD072KL)
R56  ValueDisplayed: 0  [0603]  (hidden comment: ERJ-3GEY0R00V)
R57  ValueDisplayed: 6.49  [0603]  (hidden comment: CRCW06036R49FKEA)
R58  ValueDisplayed: 10.0k  [0603]  (hidden comment: CRCW060310K0FKEA)
R59  ValueDisplayed: 100k  [0603]  (hidden comment: CRCW0603100KFKEA)
R61  ValueDisplayed: 100k  [0603]  (hidden comment: CRCW0603100KFKEA)
R63  ValueDisplayed: 6.49  [0603]  (hidden comment: CRCW06036R49FKEA)
R64  ValueDisplayed: 0  [0603]  (hidden comment: ERJ-3GEY0R00V)
R109  ValueDisplayed: 2.00k  [0603]  (hidden comment: RT0603DRD072KL)
R110  ValueDisplayed: 2.00k  [0603]  (hidden comment: RT0603DRD072KL)
R111  ValueDisplayed: 2.00k  [0603]  (hidden comment: RT0603DRD072KL)
R112  ValueDisplayed: 0  [0603]  (hidden comment: ERJ-3GEY0R00V)
R113  ValueDisplayed: 2.00k  [0603]  (hidden comment: RT0603DRD072KL)
R114  ValueDisplayed: 0  [0603]  (hidden comment: ERJ-3GEY0R00V)
R115  ValueDisplayed: 2.00k  [0603]  (hidden comment: RT0603DRD072KL)
TP3  5000  [Keystone5000]
TP4  5000  [Keystone5000]
U1  ADS131M08IRSNR  [RSN0032B-MFG]
U9  TMAG5273A2QDBVR  [DBV0006A-MFG]

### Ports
ADS_CS (in), ADS_DIN_MSP_DOUT (in), ADS_DOUT_MSP_DIN (out), ADS_DRDY (out), ADS_SYNC_RESET (in), M0_CLKOUT (in), SPI_SCK (in), TMAG_INT (out), TMAG_SCL (bidir), TMAG_SDA (bidir)

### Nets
GND: C1.2 C3.1 C4.2 C5.2 C6.2 C7.2 C9.1 C10.2 C12.1 C13.2 C15.1 C16.2 C18.1 C19.2 C21.1 C45.2 C46.2 C47.2 C49.1 J4.2 J5.2 J6.2 J15.2 R7.1 R8.1 R9.2 R17.1 R19.1 R21.2 R32.1 R33.1 R34.2 R37.1 R38.2 R43.1 R44.2 R49.1 R50.2 R57.1 R63.2 TP3.1 TP4.1 U1.13(AGND) U1.25(DGND) U1.28(AGND) U1.33(EP) U9.2(GND) U9.3(GND(TEST))
VDD_3V3: C5.1 C6.1 C46.1 R58.1 R59.2 R61.2 R109.2 R110.2 R111.2 U1.15(AVDD) U1.26(DVDD) U9.4(VCC)  [project net VCC_EXTERN]
ADS_CS: R29.2 R59.1 ; port ADS_CS
ADS_DIN_MSP_DOUT: R18.2 ; port ADS_DIN_MSP_DOUT
ADS_DOUT_MSP_DIN: R20.2 ; port ADS_DOUT_MSP_DIN
ADS_DRDY: R23.2 R58.2 ; port ADS_DRDY
ADS_SYNC_RESET: R30.2 R61.1 ; port ADS_SYNC_RESET
CLKIN_ADS_T: C45.1 J11.1 R15.1 U1.23(XTAL1/CLKIN)
CS_ADS_T: J11.6 R29.1 U1.17(~{CS})
DIN_ADS_T: J11.2 R18.1 U1.21(DIN)
DOUT_ADS_T: J11.3 R20.1 U1.20(DOUT)
DRDY_ADS_T: J11.5 R23.1 U1.18(~{DRDY})
I_Neutral_N: C48.2 C49.2 R115.2 U1.10(AIN6N)
I_Neutral_P: C47.1 C48.1 R113.2 U1.9(AIN6P)
I_Phase_A_N: C14.2 C15.2 R40.2 U1.3(AIN3N)
I_Phase_A_P: C13.1 C14.1 R36.2 U1.4(AIN3P)
I_Phase_B_N: C17.2 C18.2 R46.2 U1.6(AIN4N)
I_Phase_B_P: C16.1 C17.1 R42.2 U1.5(AIN4P)
I_Phase_C_N: C20.2 C21.2 R52.2 U1.7(AIN5N)
I_Phase_C_P: C19.1 C20.1 R48.2 U1.8(AIN5P)
M0_CLKOUT: R15.2 ; port M0_CLKOUT
SCK_ADS_T: J11.4 R22.1 U1.19(SCLK)
SPI_SCK: R22.2 ; port SPI_SCK
SYNC_RESET_ADS_T: J11.7 R30.1 U1.16(~{SYNC}/~{RESET})
TMAG_INT: R111.1 U9.5(~{INT}) ; port TMAG_INT
TMAG_SCL: R109.1 U9.1(SCL) ; port TMAG_SCL
TMAG_SDA: R110.1 U9.6(SDA) ; port TMAG_SDA
V_Phase_A_N: C2.2 C3.2 R8.2 U1.30(AIN0N)
V_Phase_A_P: C1.1 C2.1 R5.2 U1.29(AIN0P)
V_Phase_B_N: C8.2 C9.2 R19.2 U1.31(AIN1N)
V_Phase_B_P: C7.1 C8.1 R14.2 U1.32(AIN1P)
V_Phase_C_N: C11.2 C12.2 R33.2 U1.2(AIN2N)
V_Phase_C_P: C10.1 C11.1 R28.2 U1.1(AIN2P)
NetC4_1: C4.1 U1.24(CAP)
NetJ1_1: J1.1 R1.1 R6.1
NetJ1_2: J1.2 R6.2 R9.1
NetJ2_1: J2.1 R10.1 R16.1
NetJ2_2: J2.2 R16.2 R21.1
NetJ3_1: J3.1 R24.1 R31.1
NetJ3_2: J3.2 R31.2 R34.1
NetJ4_1: J4.1 R35.1
NetJ4_3: J4.3 R39.1
NetJ5_1: J5.1 R41.1
NetJ5_3: J5.3 R45.1
NetJ6_1: J6.1 R47.1
NetJ6_3: J6.3 R51.1
NetJ15_1: J15.1 R56.1
NetJ15_3: J15.3 R64.1
NetR1_2: R1.2 R2.2
NetR2_1: R2.1 R3.2
NetR3_1: R3.1 R4.1
NetR4_2: R4.2 R5.1 R7.2
NetR10_2: R10.2 R11.2
NetR11_1: R11.1 R12.2
NetR12_1: R12.1 R13.1
NetR13_2: R13.2 R14.1 R17.2
NetR24_2: R24.2 R25.2
NetR25_1: R25.1 R26.2
NetR26_1: R26.1 R27.1
NetR27_2: R27.2 R28.1 R32.2
NetR35_2: R35.2 R36.1 R37.2
NetR38_1: R38.1 R39.2 R40.1
NetR41_2: R41.2 R42.1 R43.2
NetR44_1: R44.1 R45.2 R46.1
NetR47_2: R47.2 R48.1 R49.2
NetR50_1: R50.1 R51.2 R52.1
NetR56_2: R56.2 R112.1
NetR57_2: R57.2 R112.2 R113.1
NetR63_1: R63.1 R114.2 R115.1
NetR64_2: R64.2 R114.1

Not connected (* = marked no-connect by the designer): J11 8; U1 11(AIN7N)* 12(AIN7P)* 14(REFIN)* 22(XTAL2)* 27(NC)*

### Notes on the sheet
- Magnetic Tampering Detection + Input Filter for Neutral Tampering Detection

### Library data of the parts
C1 C3 C7 C9 C10 C12 C13 C15 C16 C18 C19 C21 C45 C47 C49 = CMP-0084283-1: CAP, CERM, 10 pF, 100 V,+/- 5%, C0G/NP0, AEC-Q200 Grade 1, 0603; Manufacturer: MuRata; TaMax_C: 125°C; SizeX_mm: 1.6; SizeY_mm: 0.8; SizeArea_mm2: 1.28; Polarized: N; AEC Category: Q200; SizeAreaWB_mm2: 4.68; AEC Qualified: Y; SizeZ_mm: 1; Value: 10pF; U/M: EA; TaMin_C: -55°C
C2 C8 C11 = CMP-0084514-1: CAP, CERM, 6800 pF, 100 V,+/- 5%, C0G/NP0, AEC-Q200 Grade 0, 0603; Manufacturer: TDK; U/M: EA; SizeAreaWB_mm2: 4.68; Value: 6800pF; Polarized: N; AEC Qualified: Y; TaMax_C: 150°C; AEC Grade: 0; SizeX_mm: 1.6; Cap_F: 6.8nF; TaMin_C: -55°C; SizeZ_mm: 1; SizeY_mm: 0.8; AEC Category: Q200; SizeArea_mm2: 1.28
C4 = CMP-0092769-1: Cap Ceramic 220nF 16V X7R 10% Pad SMD 0402 +125°C Automotive T/R; Manufacturer: TDK Corporation; Tolerance_%: 0.1%; AEC Qualified: Yes; AEC Grade: Grade 1; TempCo: 15%; SizeZ_mm: 0.55mm
C5 C6 = CMP-0079607-1: CAP, CERM, 1 µF, 16 V,+/- 10%, X7R, AEC-Q200 Grade 1, 0603; Manufacturer: TDK; TaMin_C: -55°C; Polarized: N; SizeAreaWB_mm2: 4.68; U/M: EA; Value: 1uF; TaMax_C: 125°C; SizeZ_mm: 1; SizeX_mm: 1.6; SizeY_mm: 0.8; Value2: 16V; SizeArea_mm2: 1.28; AEC Qualified: Y; AEC Category: Q200
C14 C17 C20 C48 = CMP-0007487-4: CAP, CERM, 6800 pF, 100 V, +/- 10%, X7R, 0603; Manufacturer: MuRata; PartNumber: GRM188R72A682KA01D; TaMin_C: -55°C; Polarized: N; SizeAreaWB_mm2: 4.68; Value1: Unknown; U/M: EA; Value: 6800pF; TaMax_C: 125°C; SizeZ_mm: 1; SizeX_mm: 1.6; SizeY_mm: 0.8; SizeArea_mm2: 1.28; CompType: Capacitor; Cap_F: 6.8nF; AEC Category: Q200
C46 = CMP-0006979-5: CAP, CERM, 0.1 uF, 25 V, +/- 10%, X7R, 0603; Manufacturer: Kemet; TaMin_C: -55°C; Polarized: N; SizeAreaWB_mm2: 4.68; Value1: Unknown; U/M: EA; Value: 0.1uF; TaMax_C: 125°C; SizeZ_mm: 1; SizeX_mm: 1.6; SizeY_mm: 0.8; Value2: 25V; SizeArea_mm2: 1.28; AEC Category: Q200
H_IA1 H_IA2 H_IB1 H_IB2 H_IC1 H_IC2 = CMP-0079299-1: 3.5 mm PCB Hole; Manufacturer: Any; CompType: Pad
J1-J3 = CMP-0074910-1: Terminal Block, 5.08 mm, 2x1, Brass, TH; Manufacturer: On-Shore Technology; Cert_VDE: Y; CNHeader: False; Current_A: 15A; Green_Lifecycle: Not Set; Shrouded: N; Gender: Female; Green_REACh: Incomplete; Voltage_V: 300V; Row_Count: 1; Pitch_mm: 5.08; CT: True
J4-J6 J15 = CMP-0074911-1: Terminal Block, 5.08 mm, 3x1, Brass, TH; Manufacturer: On-Shore Technology; Cert_VDE: Y; CNHeader: False; Current_A: 15A; Green_Lifecycle: Not Set; Shrouded: N; Gender: Female; Green_REACh: Incomplete; Voltage_V: 300V; Row_Count: 1; Pitch_mm: 5.08; CT: True
J11 = CMP-0055090-1: Header, 100mil, 8x1, TH; Manufacturer: Mill-Max; CT: FALSE; CNHeader: TRUE
R1 R9 R10 R21 R24 R34 R35 R39 R41 R45 R47 R51 R56 R64 R112 R114 = CMP-0025874-4: RES, 0, 5%, 0.1 W, AEC-Q200 Grade 0, 0603; Manufacturer: Panasonic; Power_W: 100mW; TempCo: 600 ppm/C; Value_Code: 0000; Value: 0; EIA_Code: E24; SizeX_mm: 1.6; SizeY_mm: 0.8; SizeZ_mm: 1; Value2: 0.1W; SizeArea_mm2: 1.28; AEC Qualified: Y; VDC_V: 50V; AEC Category: Q200; SizeAreaWB_mm2: 4.68
R2-R4 R11-R13 R25-R27 = CMP-0023521-3: RES, 330 k, 0.1%, 0.1 W, 0603; Manufacturer: Susumu Co Ltd; Power_W: 100mW; TempCo: 25 ppm/C; U/M: EA; Value: 330k; SizeX_mm: 1.6; SizeY_mm: 0.8; SizeZ_mm: 1; Value2: 0.1W; SizeArea_mm2: 1.28; VDC_V: 75V; AEC Category: Q200
R5 R8 R14 R19 R28 R33 = CMP-0084355-1: RES, 1.00 k, 0.5%, 0.1 W, 0603; Manufacturer: Yageo; SizeArea_mm2: 1.28; Value2: 0.1W; Res_ohm: 1k; Power_W: 100mW; EIA_Code: E192; SizeAreaWB_mm2: 4.68; TempCo: 25 ppm/C; SizeY_mm: 0.8; SizeX_mm: 1.6; AEC Qualified: N; Value_Code: 1k00; SizeZ_mm: 1; AEC Category: Q200; Value: 1.00k
R6 R16 R31 = CMP-0001856-2: Varistor 275 VAC, 100 A, TH; Manufacturer: TDK; Value: 275VAC
R7 R17 R32 = CMP-0025554-3: RES, 750, 0.5%, 0.1 W, 0603; Manufacturer: Yageo America; Power_W: 100mW; TempCo: 50 ppm/C; Value_Code: 750R; U/M: EA; Value: 750; EIA_Code: E192; SizeX_mm: 1.6; SizeY_mm: 0.8; SizeZ_mm: 1; Value2: 0.1W; SizeArea_mm2: 1.28; CompType: Resistor; VDC_V: 75V; AEC Category: Q200
R15 = CMP-0026908-3: RES, 33, 5%, 0.063 W, AEC-Q200 Grade 0, 0402; Manufacturer: Vishay-Dale; Power_W: 63mW; TempCo: 200 ppm/C; Value_Code: 33R0; Value: 33; EIA_Code: E24; SizeX_mm: 1; SizeY_mm: 0.5; SizeZ_mm: 0.6; Value2: 0.063W; AEC Qualified: Y; VDC_V: 50V; AEC Category: Q200; AEC Grade: 0
R18 R20 R22 R23 R30 = CMP-0026908-2: RES, 33, 5%, 0.063 W, 0402; Manufacturer: Vishay-Dale; Power_W: 63mW; TempCo: 200 ppm/C; Value_Code: 33R0; U/M: EA; Value: 33; EIA_Code: E24; SizeX_mm: 1; SizeY_mm: 0.5; SizeZ_mm: 0.6; Value2: 0.063W; VDC_V: 50V; AEC Category: Q200
R29 = CMP-0026822-3: RES, 0, 5%, 0.063 W, AEC-Q200 Grade 0, 0402; Manufacturer: Vishay-Dale; Power_W: 63mW; TempCo: 200 ppm/C; Value_Code: 0000; Value: 0; EIA_Code: E24; SizeX_mm: 1; SizeY_mm: 0.5; SizeZ_mm: 0.6; Value2: 0.063W; AEC Qualified: Y; VDC_V: 50V; AEC Category: Q200
R36 R40 R42 R46 R48 R52 R109-R111 R113 R115 = CMP-0025080-3: RES, 2.00 k, 0.5%, 0.1 W, 0603; Manufacturer: Yageo America; Power_W: 100mW; TempCo: 25 ppm/C; Value_Code: 2k00; U/M: EA; Value: 2.00k; EIA_Code: E192; Res_ohm: 2k; SizeX_mm: 1.6; SizeY_mm: 0.8; SizeZ_mm: 1; Value2: 0.1W; SizeArea_mm2: 1.28; CompType: Resistor; VDC_V: 75V; AEC Category: Q200
R37 R38 R43 R44 R49 R50 R57 R63 = CMP-0022575-4: RES, 6.49, 1%, 0.1 W, AEC-Q200 Grade 0, 0603; Manufacturer: Vishay-Dale; Power_W: 100mW; TempCo: 100 ppm/C; Value_Code: 6R49; Value: 6.49; EIA_Code: E96; SizeX_mm: 1.6; SizeY_mm: 0.8; SizeZ_mm: 1; Value2: 0.1W; SizeArea_mm2: 1.28; AEC Qualified: Y; VDC_V: 75V; AEC Category: Q200; AEC Grade: 0
R58 = CMP-0021998-2: RES, 10.0 k, 1%, 0.1 W, 0603; Manufacturer: Vishay-Dale; Power_W: 100mW; TempCo: 100 ppm/C; Value_Code: 10k0; U/M: EA; Value: 10.0k; EIA_Code: E96; Res_ohm: 10k; SizeX_mm: 1.6; SizeY_mm: 0.8; SizeZ_mm: 1; Value2: 0.1W; SizeArea_mm2: 1.28; VDC_V: 75V; AEC Category: Q200
R59 R61 = CMP-0021990-4: RES, 100 k, 1%, 0.1 W, AEC-Q200 Grade 0, 0603; Manufacturer: Vishay-Dale; Power_W: 100mW; TempCo: 100 ppm/C; Value: 100k; EIA_Code: E96; SizeX_mm: 1.6; SizeY_mm: 0.8; SizeZ_mm: 1; Value2: 0.1W; SizeArea_mm2: 1.28; AEC Qualified: Y; VDC_V: 75V; AEC Category: Q200; AEC Grade: 0
TP3 TP4 = CMP-0055137-1: as TP1 on sheet TIDA_010243-MCU
U1 = CMP-0089590-1: 8-Channel, Simultaneously-Sampling, 24-Bit, Delta-Sigma ADC; Manufacturer: Texas Instruments; Data Polarity: Differential; TJmax_C: +150°C; Resolution: 24bits; Sampling Rate: 32ksps; Standoff Height: 0mm; Interface: SPI; Min Supply Voltage: 1.65V; SizeZ_mm: 0.8mm; TaMin_C: -40°C; Number Of Converters: 1; Number Of Channels: 8; TaMax_C: +125°C; AEC Qualified: No; Max Supply Voltage: 3.6V
U9 = CMP-0092928-2: 3-Axis Linear Hall Effect Sensor With I2C Interface SOT23-6; Manufacturer: Texas Instruments; Standoff Height: 0mm; TaMin_C: -40°C; CompType: IC; AEC Qualified: No; Operating Supply Current: 2.3-2.7mA; Min Supply Voltage: 1.7V; SizeZ_mm: 1.45mm; Max Supply Voltage: 3.6V; AEC Category: Q200; TaMax_C: +125°C; TJmax_C: +150°C; AEC Grade: NA

## Sheet TIDA-010243_Interfaces.SchDoc
size 431 x 279 mm; Date: Not shown in title block; ApprovedBy: Not shown in title block; CheckedBy: Not shown in title block; Author: Not shown in title block; CompanyName: Not shown in title block; Engineer: Not shown in title block; Organization: Not shown in title block; Address1: Not shown in title block; Address2: Not shown in title block; Address3: Not shown in title block; Address4: Not shown in title block; DocumentNumber: 1; Revision: Use project parameter SCH_Rev; SheetNumber: 3; SheetTotal: 4; PageSetup: Record=PageOptions¦CenterHorizontal=True¦CenterVertical=True¦PrintScale=1.00¦XCorrection=1.00¦YCorrection=1.00¦PrintKind=0¦BorderSize=5000000¦LeftOffset=0¦BottomOffset=0¦Orientation=2¦PaperLength=1000¦PaperWidth=1000¦Scale=100¦PaperSource=15¦PrintQuality=600¦MediaType=1¦DitherType=10¦PaperKind=Letter¦PrintScaleMode=1
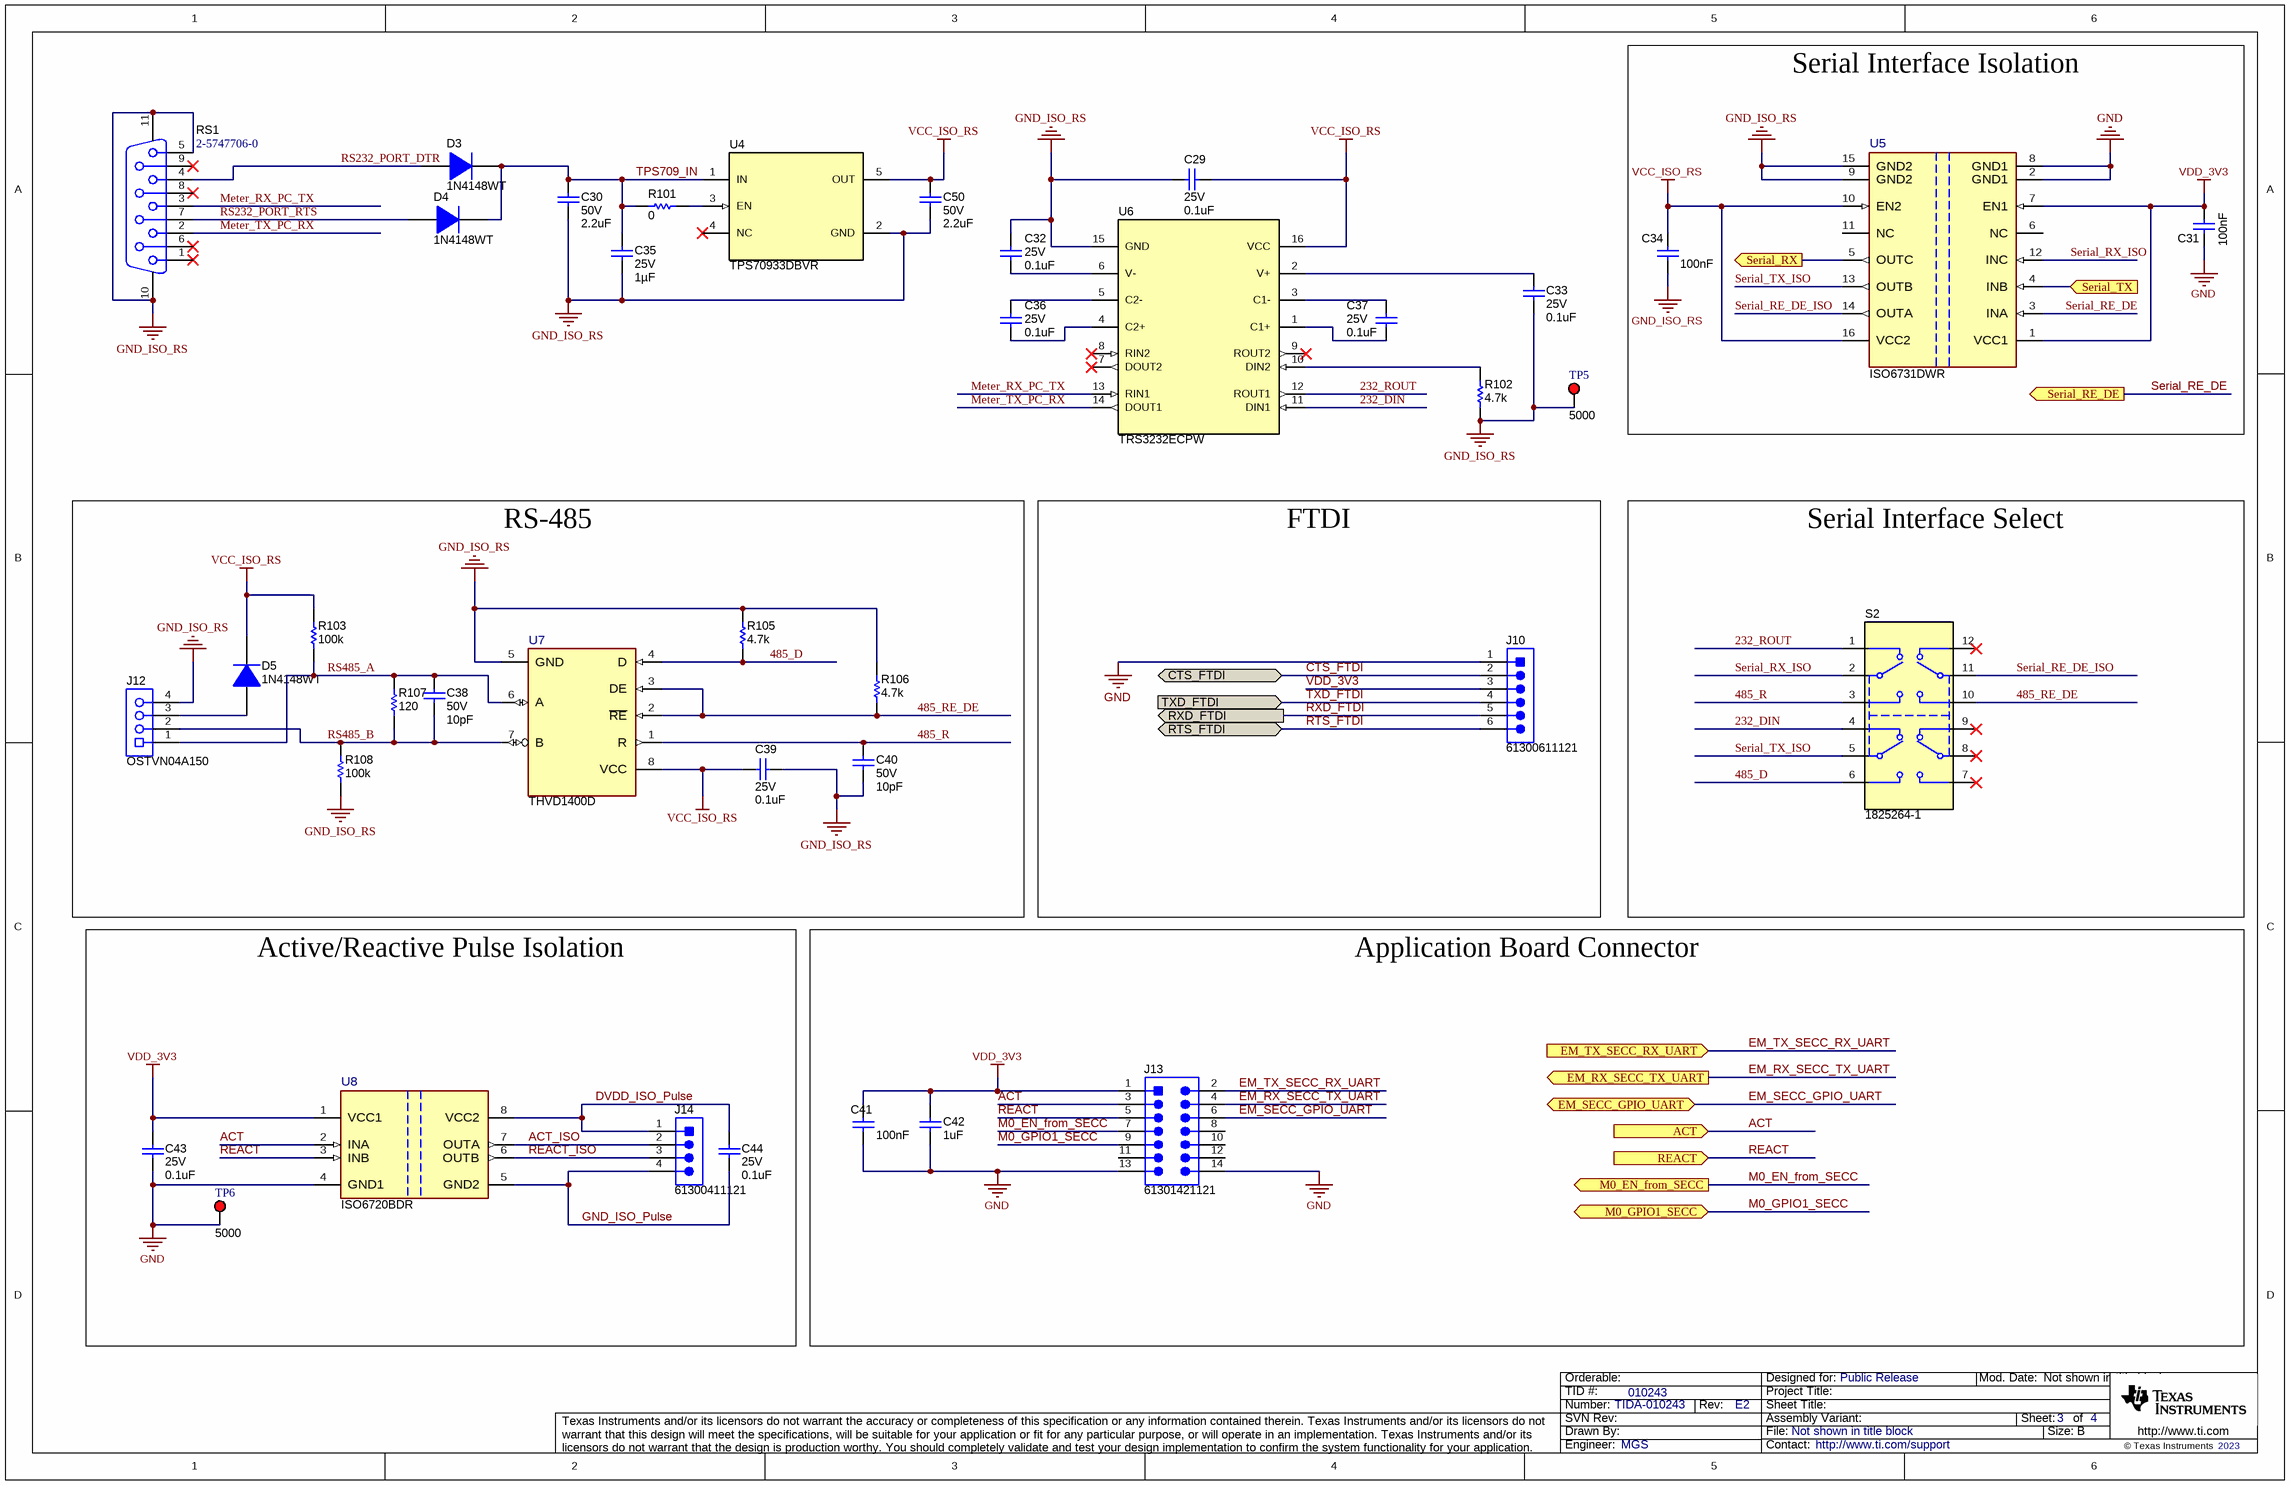
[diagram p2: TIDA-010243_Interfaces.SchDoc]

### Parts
C29  VDC_V: 25V  ValueDisplayed: 0.1uF  [0603]  (hidden comment: CGA3E2X8R1E104K080AA)
C30  VDC_V: 50V  ValueDisplayed: 2.2uF  [0603]  (hidden comment: GRT188R61H225KE13D)
C31  Cap_F: 100nF  [0603]  (hidden comment: C0603X104K3RACTU)
C32  VDC_V: 25V  ValueDisplayed: 0.1uF  [0603]  (hidden comment: CGA3E2X8R1E104K080AA)
C33  VDC_V: 25V  ValueDisplayed: 0.1uF  [0603]  (hidden comment: CGA3E2X8R1E104K080AA)
C34  Cap_F: 100nF  [0603]  (hidden comment: C0603X104K3RACTU)
C35  VDC_V: 25V  ValueDisplayed: 1µF  [0603]  (hidden comment: CGA3E1X7R1E105M080AC)
C36  VDC_V: 25V  ValueDisplayed: 0.1uF  [0603]  (hidden comment: CGA3E2X8R1E104K080AA)
C37  VDC_V: 25V  ValueDisplayed: 0.1uF  [0603]  (hidden comment: CGA3E2X8R1E104K080AA)
C38  VDC_V: 50V  ValueDisplayed: 10pF  [0603]  (hidden comment: CGA3E2C0G1H100D080AA)
C39  VDC_V: 25V  ValueDisplayed: 0.1uF  [0603]  (hidden comment: CGA3E2X8R1E104K080AA)
C40  VDC_V: 50V  ValueDisplayed: 10pF  [0603]  (hidden comment: CGA3E2C0G1H100D080AA)
C41  Cap_F: 100nF  [0603]  (hidden comment: C0603X104K3RACTU)
C42  ValueDisplayed: 1uF  [0603]  (hidden comment: C0603C105K3RACTU)
C43  VDC_V: 25V  ValueDisplayed: 0.1uF  [0603]  (hidden comment: CGA3E2X8R1E104K080AA)
C44  VDC_V: 25V  ValueDisplayed: 0.1uF  [0603]  (hidden comment: CGA3E2X8R1E104K080AA)
C50  VDC_V: 50V  ValueDisplayed: 2.2uF  [0603]  (hidden comment: GRT188R61H225KE13D)
D3  1N4148WT  [Fairchild_SOD-523F]
D4  1N4148WT  [Fairchild_SOD-523F]
D5  1N4148WT  [Fairchild_SOD-523F]
J10  61300611121  [WURTH_61300611121]
J12  OSTVN04A150  [On-Shore_OSTVN04A150]
J13  61301421121  [Wurth_61301421121]
J14  61300411121  [WURTH_61300411121]
R101  ValueDisplayed: 0  [0402]  (hidden comment: RC0402JR-070RL)
R102  ValueDisplayed: 4.7k  [0603]  (hidden comment: CRCW06034K70JNEA)
R103  ValueDisplayed: 100k  [0603]  (hidden comment: CRCW0603100KJNEA)
R105  ValueDisplayed: 4.7k  [0603]  (hidden comment: CRCW06034K70JNEA)
R106  ValueDisplayed: 4.7k  [0603]  (hidden comment: CRCW06034K70JNEA)
R107  ValueDisplayed: 120  [0603]  (hidden comment: RT0603DRE07120RL)
R108  ValueDisplayed: 100k  [0603]  (hidden comment: CRCW0603100KJNEA)
RS1  2-5747706-0  [TE_2-5747706-0]
S2  1825264-1  [SW_1825264-1]
TP5  5000  [Keystone5000]
TP6  5000  [Keystone5000]
U4  TPS70933DBVR  [DBV0005A_N]
U5  ISO6731DWR  [DW0016A-MFG]
U6  TRS3232ECPW  [PW0016A_L]
U7  THVD1400D  [D0008B-MFG]
U8  ISO6720BDR  [D0008A-MFG]

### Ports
ACT (in), CTS_FTDI (bidir), EM_RX_SECC_TX_UART (out), EM_SECC_GPIO_UART (bidir), EM_TX_SECC_RX_UART (in), M0_EN_from_SECC (out), M0_GPIO1_SECC (bidir), REACT (in), RTS_FTDI (bidir), RXD_FTDI (out), Serial_RE_DE (out), Serial_RX (out), Serial_TX (in), TXD_FTDI (in)

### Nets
GND: C31.2 C41.2 C42.1 C43.2 J10.1 J13.13 J13.14 TP6.1 U5.2(GND1) U5.8(GND1) U8.4(GND1)
GND_ISO_RS: C29.1 C30.2 C32.1 C33.1 C34.2 C35.2 C39.2 C40.1 C50.2 J12.4 R102.1 R105.2 R106.2 R108.1 RS1.5 RS1.10 RS1.11 TP5.1 U4.2(GND) U5.9(GND2) U5.15(GND2) U6.15(GND) U7.5(GND)
VCC_ISO_RS: C29.2 C34.1 C39.1 C50.1 D5.1(K) R103.2 U4.5(OUT) U5.10(EN2) U5.16(VCC2) U6.16(VCC) U7.8(VCC)
VDD_3V3: C31.1 C41.1 C42.2 C43.1 J10.3 J13.1 U5.1(VCC1) U5.7(EN1) U8.1(VCC1)  [project net VCC_EXTERN]
232_DIN: S2.4 U6.11(DIN1)
232_ROUT: S2.1 U6.12(ROUT1)
485_D: R105.1 S2.6 U7.4(D)
485_R: C40.2 S2.3 U7.1(R)
485_RE_DE: R106.1 S2.10 U7.2(~{RE}) U7.3(DE)
ACT: J13.3 U8.2(INA) ; port ACT
ACT_ISO: J14.2 U8.7(OUTA)
CTS_FTDI: J10.2 ; port CTS_FTDI
DVDD_ISO_Pulse: C44.1 J14.1 U8.8(VCC2)
EM_RX_SECC_TX_UART: J13.4 ; port EM_RX_SECC_TX_UART
EM_SECC_GPIO_UART: J13.6 ; port EM_SECC_GPIO_UART
EM_TX_SECC_RX_UART: J13.2 ; port EM_TX_SECC_RX_UART
GND_ISO_Pulse: C44.2 J14.4 U8.5(GND2)
M0_EN_from_SECC: J13.7 ; port M0_EN_from_SECC
M0_GPIO1_SECC: J13.9 ; port M0_GPIO1_SECC
Meter_RX_PC_TX: RS1.3 U6.13(RIN1)
Meter_TX_PC_RX: RS1.2 U6.14(DOUT1)
REACT: J13.5 U8.3(INB) ; port REACT
REACT_ISO: J14.3 U8.6(OUTB)
RS232_PORT_DTR: D3.2(A) RS1.4
RS232_PORT_RTS: D4.2(A) RS1.7
RS485_A: C38.1 J12.1 R103.1 R107.2 U7.6(A)
RS485_B: C38.2 J12.2 R107.1 R108.2 U7.7(B)
RTS_FTDI: J10.6 ; port RTS_FTDI
RXD_FTDI: J10.5 ; port RXD_FTDI
Serial_RE_DE: U5.3(INA) ; port Serial_RE_DE
Serial_RE_DE_ISO: S2.11 U5.14(OUTA)
Serial_RX: U5.5(OUTC) ; port Serial_RX
Serial_RX_ISO: S2.2 U5.12(INC)
Serial_TX: U5.4(INB) ; port Serial_TX
Serial_TX_ISO: S2.5 U5.13(OUTB)
TPS709_IN: C30.1 C35.1 D3.1(K) D4.1(K) R101.1 U4.1(IN)
TXD_FTDI: J10.4 ; port TXD_FTDI
NetC32_2: C32.2 U6.6(V-)
NetC33_2: C33.2 U6.2(V+)
NetC36_1: C36.1 U6.5(C2-)
NetC36_2: C36.2 U6.4(C2+)
NetC37_1: C37.1 U6.3(C1-)
NetC37_2: C37.2 U6.1(C1+)
NetD5_2: D5.2(A) J12.3
NetR101_2: R101.2 U4.3(EN)
NetR102_2: R102.2 U6.10(DIN2)

Not connected (* = marked no-connect by the designer): J13 8 10 11 12; RS1 1* 6* 8* 9*; S2 7* 8* 9* 12*; U4 4(NC)*; U5 6(NC) 11(NC); U6 7(DOUT2)* 8(RIN2)* 9(ROUT2)*

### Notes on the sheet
- Serial Interface Isolation
- RS-485
- (near J10) FTDI
- (near S2) Serial Interface Select
- Active/Reactive Pulse Isolation
- Application Board Connector

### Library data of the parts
C29 C32 C33 C36 C37 = CMP-0007090-4: CAP, CERM, 0.1 uF, 25 V, +/- 10%, X8R, AEC-Q200 Grade 0, 0603; Manufacturer: TDK; TaMin_C: -55°C; Polarized: N; SizeAreaWB_mm2: 4.68; Value1: Unknown; U/M: EA; Value: 0.1uF; TaMax_C: 150°C; SizeZ_mm: 1; SizeX_mm: 1.6; SizeY_mm: 0.8; SizeArea_mm2: 1.28; AEC Qualified: Y; Cap_F: 100nF; AEC Grade: 0; AEC Category: Q200
C30 C50 = CMP-0007502-5: CAP, CERM, 2.2 uF, 50 V, +/- 10%, X5R, AEC-Q200 Grade 3, 0603; Manufacturer: MuRata; TaMin_C: -55°C; Polarized: N; SizeAreaWB_mm2: 4.68; Value1: Unknown; U/M: EA; Value: 2.2uF; TaMax_C: 85°C; SizeZ_mm: 1; SizeX_mm: 1.6; SizeY_mm: 0.8; SizeArea_mm2: 1.28; CompType: Capacitor; AEC Qualified: Y; Cap_F: 2.2µF; AEC Grade: 3; AEC Category: Q200
C31 C34 C41 = CMP-0006979-5: as C46 on sheet TIDA-010243-AFE
C35 = CMP-0082113-1: CAP, CERM, 1 µF, 25 V,+/- 20%, X7R, AEC-Q200 Grade 1, 0603; Manufacturer: TDK; SizeAreaWB_mm2: 4.68; SizeArea_mm2: 1.28; AEC Qualified: Y; AEC Category: Q200; Value: 1uF; TaMax_C: 125°C; SizeZ_mm: 1; Polarized: N; TaMin_C: -55°C; SizeY_mm: 0.8; U/M: EA; SizeX_mm: 1.6
C38 C40 = CMP-0007069-4: CAP, CERM, 10 pF, 50 V, +/- 5%, C0G/NP0, AEC-Q200 Grade 1, 0603; Manufacturer: TDK; TaMin_C: -55°C; Polarized: N; SizeAreaWB_mm2: 4.68; Value1: Unknown; U/M: EA; Value: 10pF; TaMax_C: 125°C; SizeZ_mm: 1; SizeX_mm: 1.6; SizeY_mm: 0.8; SizeArea_mm2: 1.28; AEC Qualified: Y; AEC Category: Q200
C39 C43 C44 = CMP-0007090-4: CAP, CERM, 0.1 uF, 25 V, +/- 10%, X8R, AEC-Q200 Grade 0, 0603; Manufacturer: TDK; TaMin_C: -55°C; Polarized: N; SizeAreaWB_mm2: 4.68; Value1: Unknown; U/M: EA; Value: 0.1uF; TaMax_C: 150°C; SizeZ_mm: 1; SizeX_mm: 1.6; SizeY_mm: 0.8; SizeArea_mm2: 1.28; CompType: Capacitor; AEC Qualified: Y; Cap_F: 100nF; AEC Grade: 0; AEC Category: Q200
C42 = CMP-0006867-4: as C51 on sheet TIDA_010243-MCU
D3-D5 = CMP-0076982-2: Diode, Switching, 75 V, 0.3 A, SOD-523F; Manufacturer: Fairchild Semiconductor; TJmax_C: 150°C; AEC Category: Q101; SizeX_mm: 1.6; Value: 75V; Io_A: 300mA; Value1: 0.3A; Green_REACh: Incomplete; SizeZ_mm: 0.7; Green_Lifecycle: Not Set; SizeArea_mm2: 1.28; SizeAreaWB_mm2: 4.68; SizeY_mm: 0.8
J10 = CMP-0054801-2: Header, 2.54 mm, 6x1, Gold, TH; Manufacturer: Wurth Elektronik; Cert_UL: Y; Gender: Male; Row_Count: 1; Shrouded: N; Pitch_mm: 2.54
J12 = CMP-0075095-1: Terminal Block, 2.54mm, 4x1, Brass, TH; Manufacturer: On-Shore Technology; CT: True; CNHeader: False
J13 = CMP-0086014-1: Header, 2.54mm, 7x2, Gold, TH; Manufacturer: Wurth Elektronik; Pitch_mm: 2.54; Voltage_V: 250V; Shrouded: N; Gender: Male; Current_A: 3A; Cert_UL: Y; Row_Count: 2
J14 = CMP-0054798-2: Header, 2.54 mm, 4x1, Gold, TH; Manufacturer: Wurth Elektronik; Pitch_mm: 2.54; Gender: Male; Row_Count: 1; Cert_UL: Y; Shrouded: N
R101 = CMP-0027004-2: RES, 0, 5%, 0.063 W, 0402; Manufacturer: Yageo America; Power_W: 63mW; TempCo: 200 ppm/C; Value_Code: 0000; U/M: EA; Value: 0; EIA_Code: E24; SizeX_mm: 1; SizeY_mm: 0.5; SizeZ_mm: 0.6; Value2: 0.063W; VDC_V: 50V; AEC Category: Q200
R102 R105 R106 = CMP-0025817-4: RES, 4.7 k, 5%, 0.1 W, AEC-Q200 Grade 0, 0603; Manufacturer: Vishay-Dale; Power_W: 100mW; TempCo: 200 ppm/C; Value_Code: 4k70; Value: 4.7k; EIA_Code: E24; SizeX_mm: 1.6; SizeY_mm: 0.8; SizeZ_mm: 1; Value2: 0.1W; SizeArea_mm2: 1.28; AEC Qualified: Y; VDC_V: 75V; AEC Category: Q200; AEC Grade: 0
R103 R108 = CMP-0025698-4: RES, 100 k, 5%, 0.1 W, AEC-Q200 Grade 0, 0603; Manufacturer: Vishay-Dale; Power_W: 100mW; TempCo: 200 ppm/C; Value: 100k; EIA_Code: E24; SizeX_mm: 1.6; SizeY_mm: 0.8; SizeZ_mm: 1; Value2: 0.1W; SizeArea_mm2: 1.28; AEC Qualified: Y; VDC_V: 75V; AEC Category: Q200; AEC Grade: 0
R107 = CMP-0024624-2: RES, 120, 0.5%, 0.1 W, 0603; Manufacturer: Yageo America; Power_W: 100mW; TempCo: 50 ppm/C; Value_Code: 120R; U/M: EA; Value: 120; EIA_Code: E192; SizeX_mm: 1.6; SizeY_mm: 0.8; SizeZ_mm: 1; Value2: 0.1W; SizeArea_mm2: 1.28; VDC_V: 75V; AEC Category: Q200
RS1 = CMP-0079577-1: Receptacle, D-SUB-9, 2.74mm, Gold, TH; Manufacturer: TE Connectivity; Gender: Female; Cert_UL: Y; Voltage_V: 125V; Current_A: 6A; Row_Count: 2; CompType: D-Sub
S2 = CMP-0002195-2: Switch, Slide, 4PDT,TH; Manufacturer: TE Connectivity; CurrentRating_mA: 300A; PositionCount: 1; VDC_V: 30V; SwitchFunction: On-On
TP5 TP6 = CMP-0055137-1: as TP1 on sheet TIDA_010243-MCU
U4 = CMP-0073793-1: 150-mA, 30-V, Ultra-Low IQ, Wide Input Low-Dropout Regulator with Reverse Current Protection, DBV0005A (SOT-23-5); Alternate PartNumber: TPS70933DBVT; Alternate Manufacturer: Texas Instruments; Green_Lifecycle: Active; SizeAreaWB_mm2: 14.82; Green_REACh: Passed; U/M: EA; SizeZ_mm: 1.45; SizeX_mm: 2.8; SizeY_mm: 2.9; SizeArea_mm2: 8.12; CompType: IC
U5 = CMP-0094636-1: Manufacturer: Texas Instruments; Min Supply Voltage: 1.71V; TJmax_C: +150°C; Max Supply Voltage: 5.5V; Standoff Height: 0.1mm; TaMax_C: +125°C; SizeZ_mm: 2.65mm; Interface: SPI,CAN,RS-232,RS-485; TaMin_C: -40°C; AEC Qualified: No
U6 = CMP-0044123-1: 3-V to 5.5-V Multichannel RS-232 Line Driver / Receiver with ±15-kV IEC ESD Protection, 0 to 70 degC, 16-Pin TSSOP (PW), Green (RoHS & no Sb/Br); ICC(Max)(mA): 1; Drivers Per Package: 2; Supply Voltage(s)(V): 3.3 or 5.0; IEC-61000-4-2 SUPPORT: TRUE; ESD HBM(kV): +/-15
U7 = CMP-0089978-1: 500 kbps RS-485 Transceivers With ±8-kV IEC ESD Protection; Manufacturer: Texas Instruments; Interface: RS-485,RS-422; SizeZ_mm: 1.75mm; Number Of Receivers: 1; TaMax_C: +125°C; TJmax_C: +150°C; Min Supply Voltage: 4.5V; Nominal Supply Current: 275-440uA; Simplex Duplex: Half-Duplex; Standoff Height: 0.11mm; Max Supply Voltage: 5.5V; TaMin_C: -40°C; Data Rate: 500kbits/s; AEC Qualified: No
U8 = CMP-0095064-1: Manufacturer: Texas Instruments; AEC Qualified: No; TaMax_C: +125°C; Standoff Height: 0.11mm; TaMin_C: -40°C; Max Supply Voltage: 5.5V; TJmax_C: +150°C; SizeZ_mm: 1.75mm; Min Supply Voltage: 1.71V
